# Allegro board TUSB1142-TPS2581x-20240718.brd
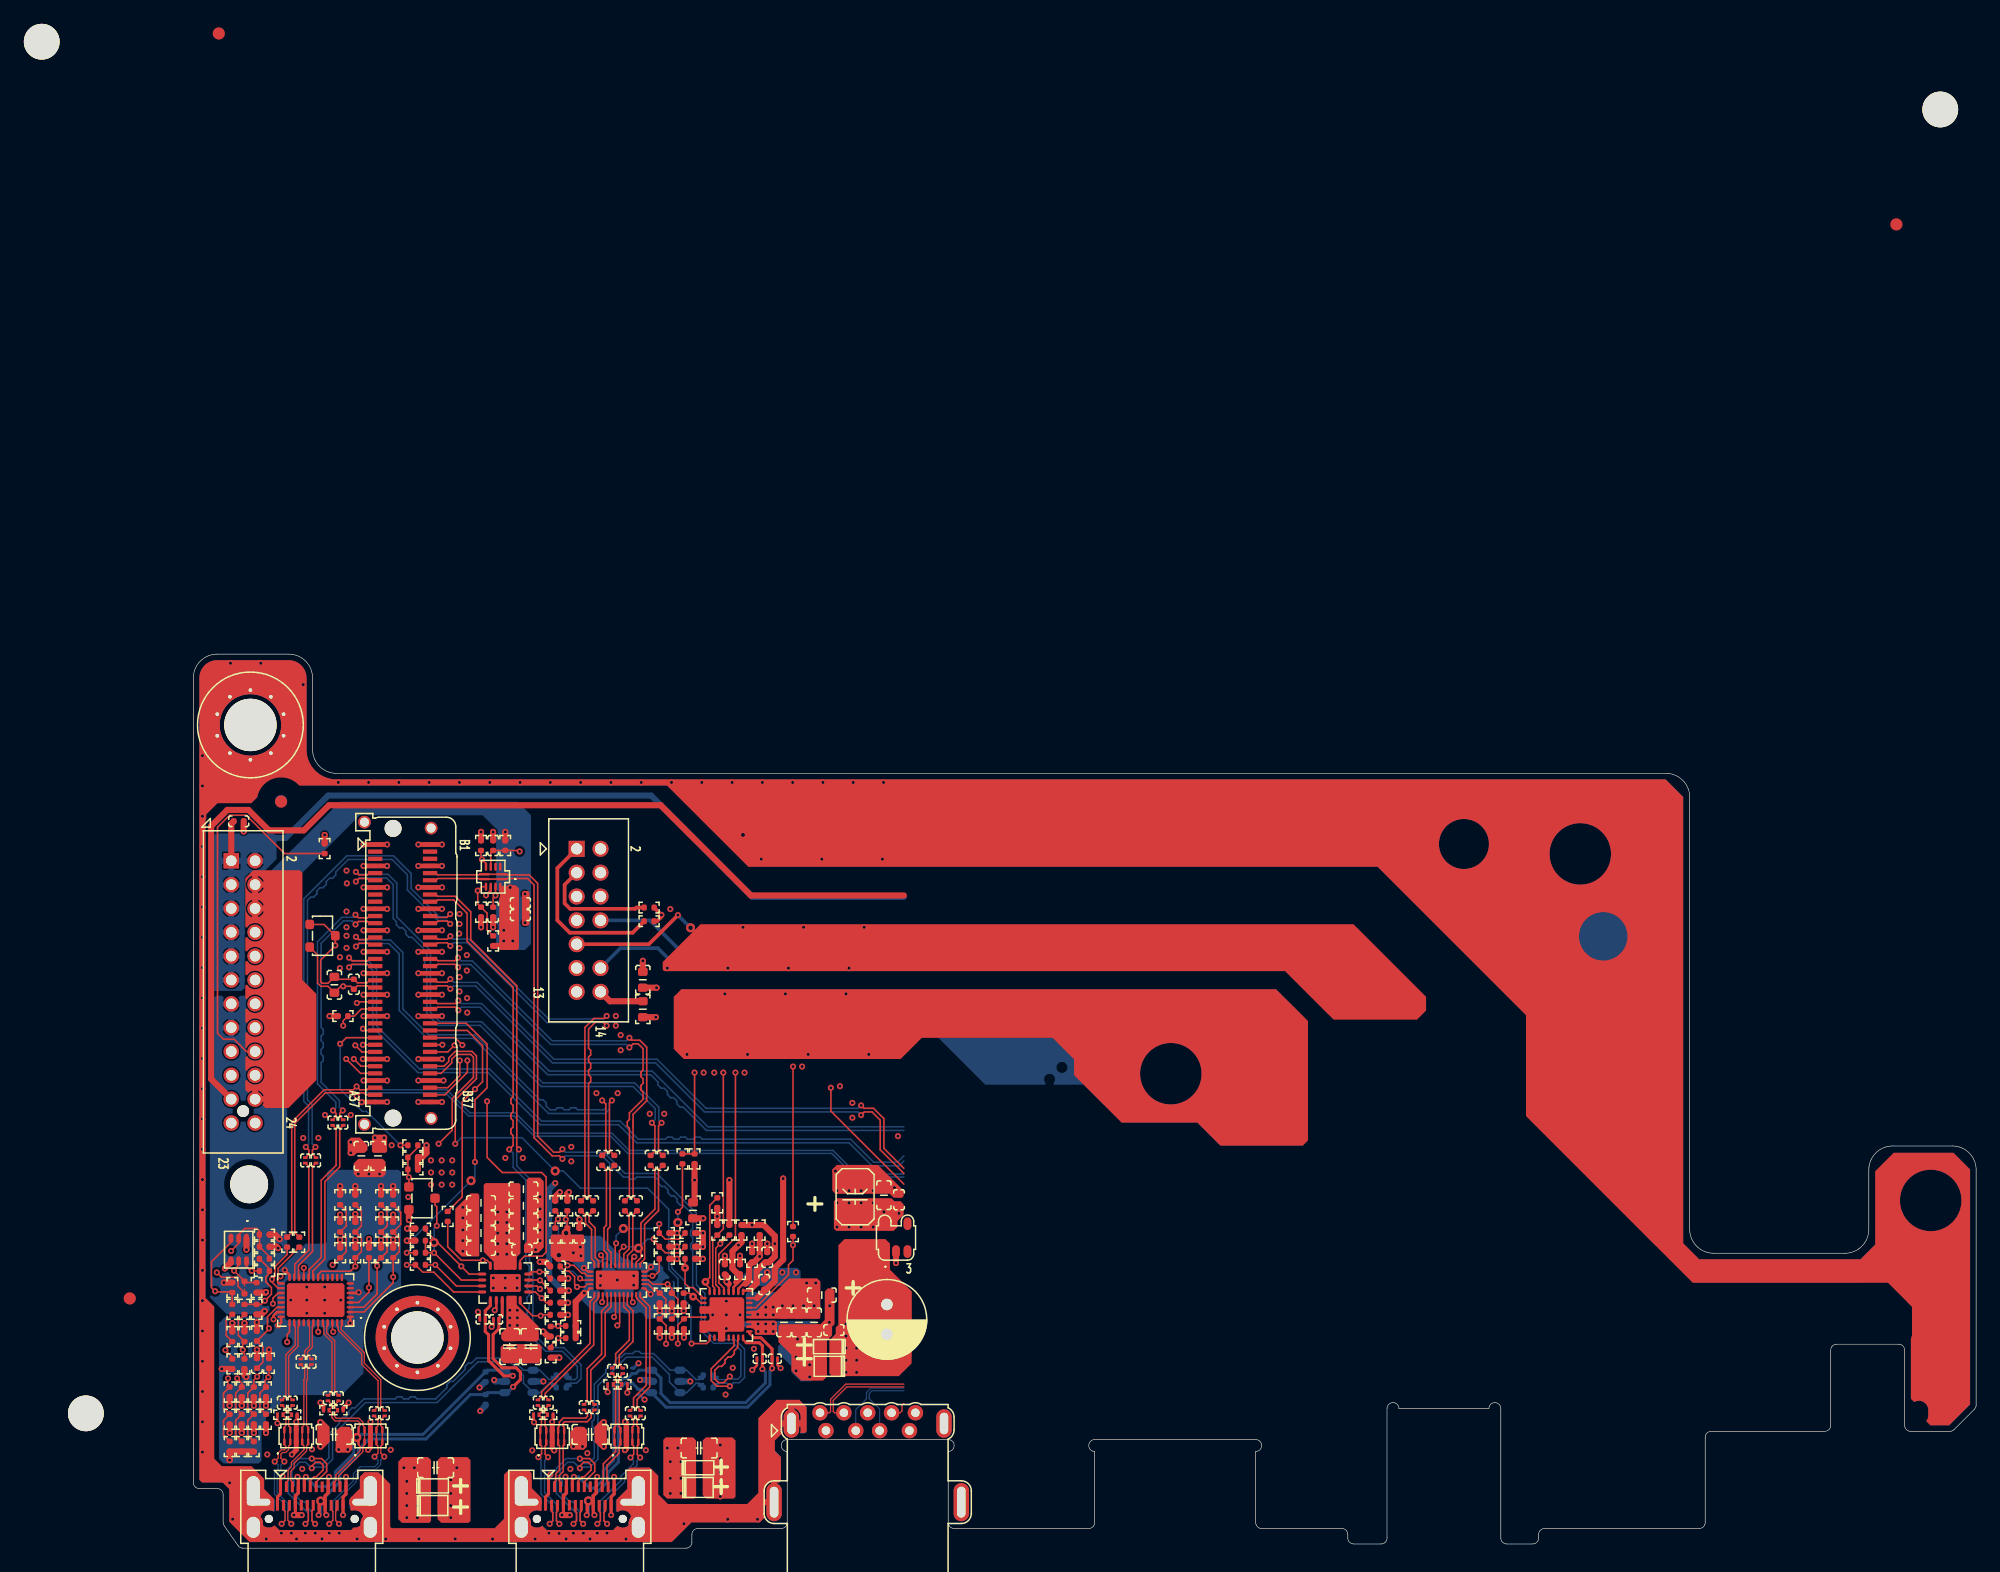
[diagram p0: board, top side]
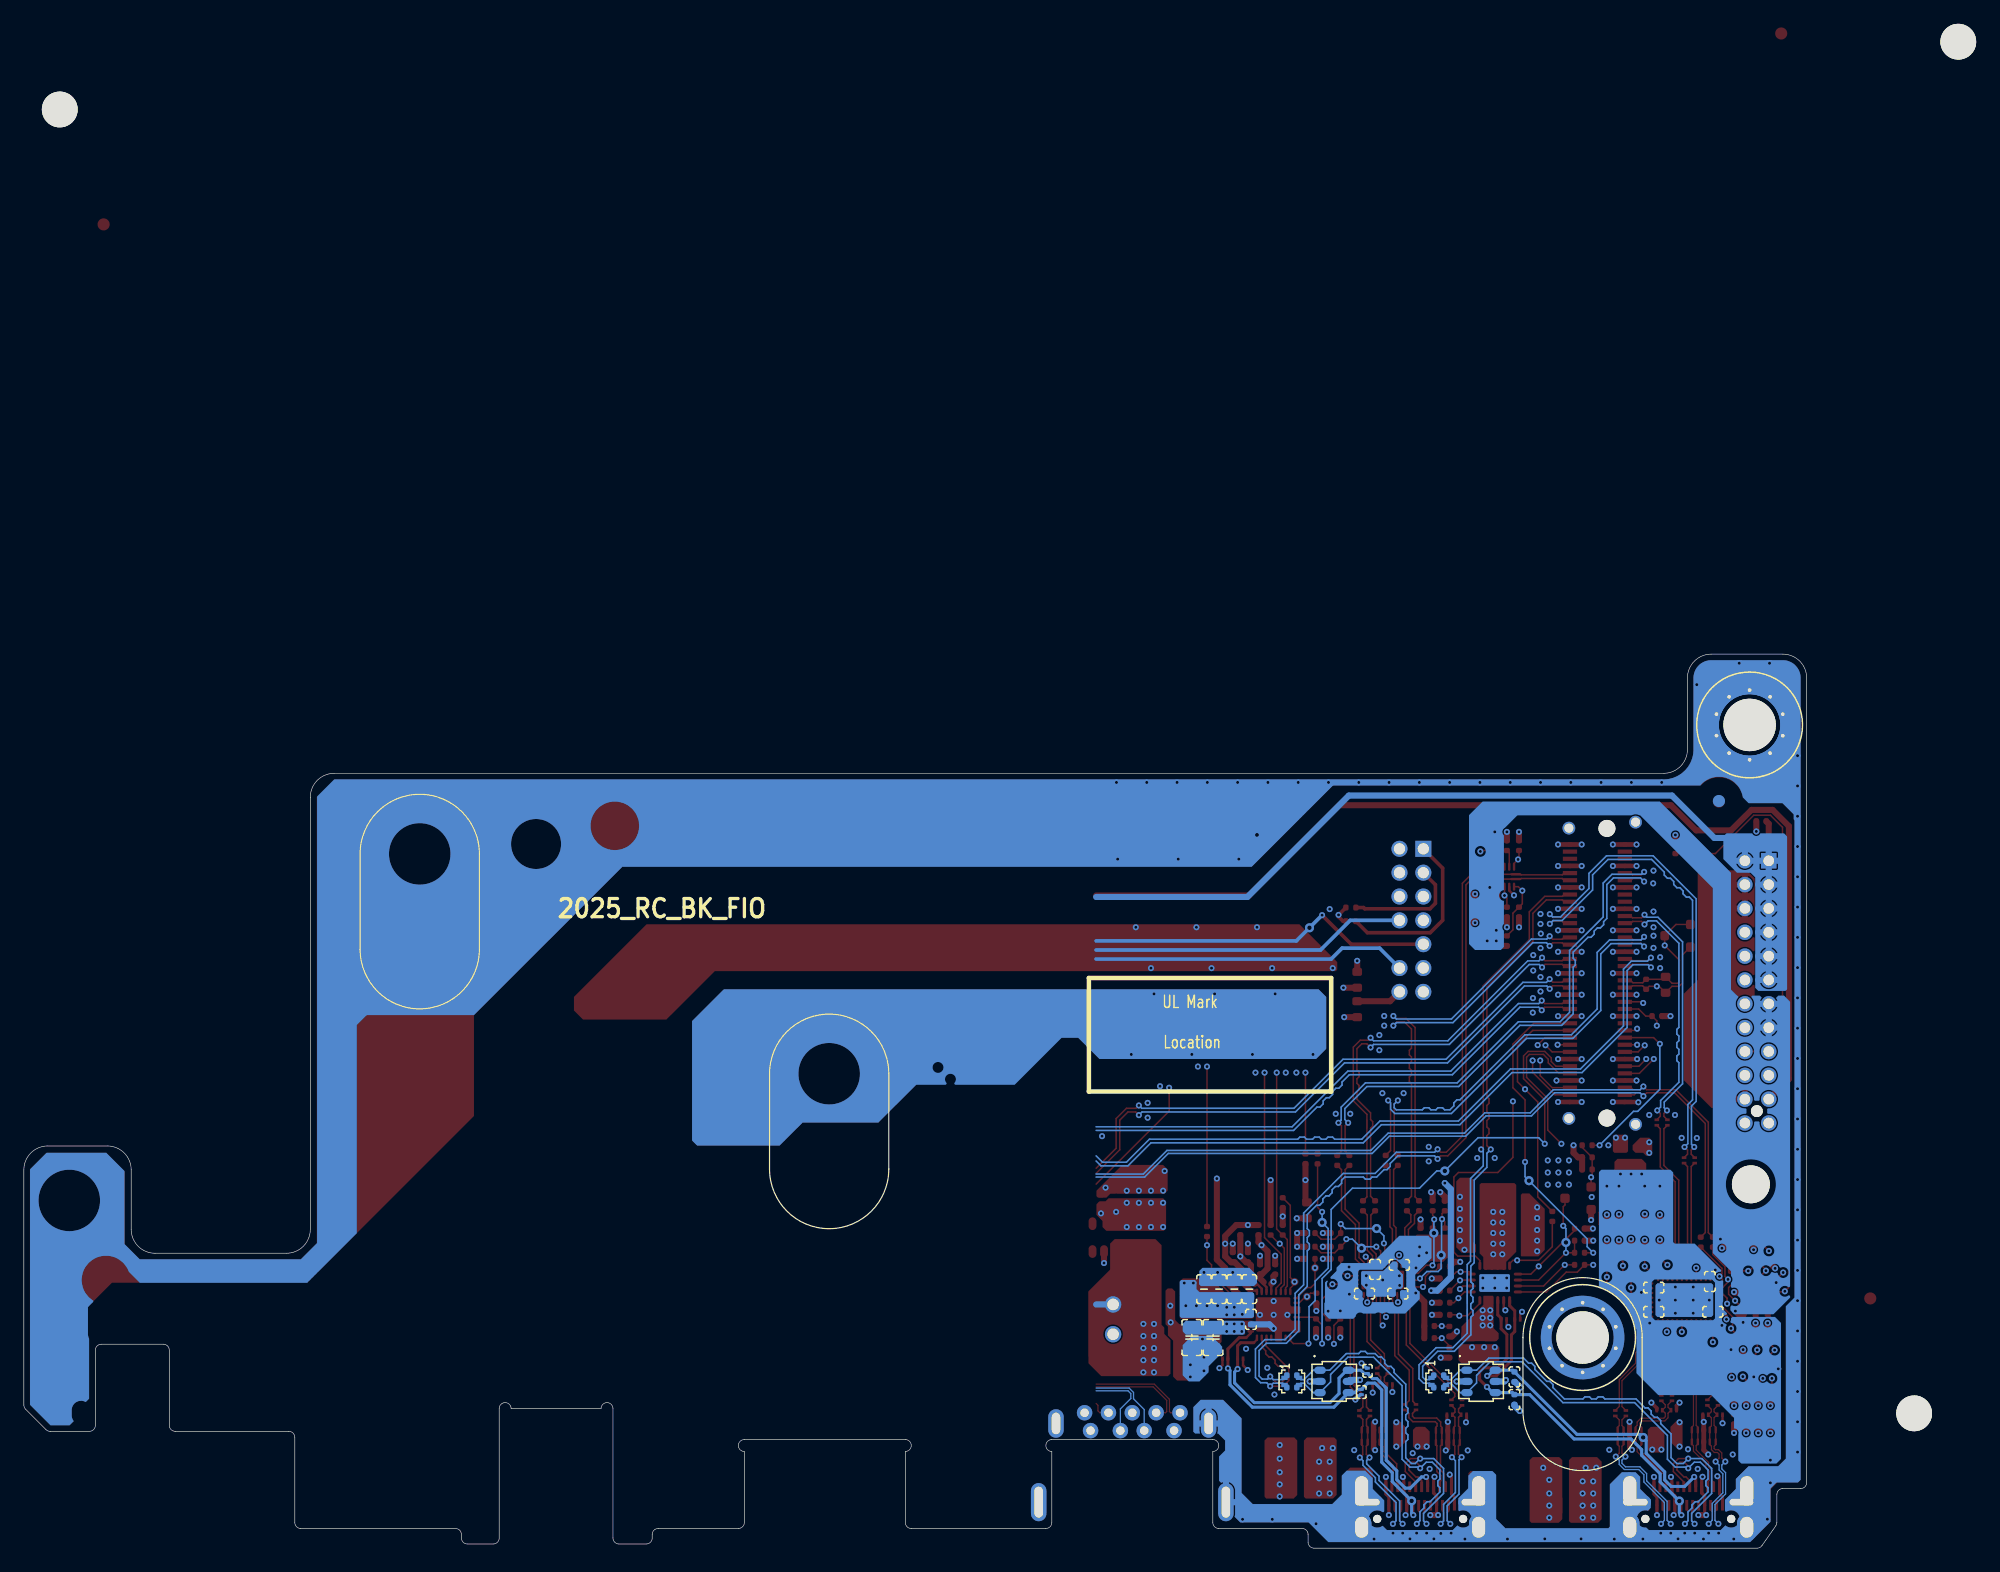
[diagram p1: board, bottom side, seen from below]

Outline 149.5 x 75 mm; copper layers: TOP, L2_GND1, L3_IN1, L4_VCC, L5_GND2, BOTTOM. Coordinates in mm from the lower left corner of the outline.
Outline path: 0,73 arc(0.59,74.41) 2,75 8,75 arc(9.41,74.41) 10,73 10,67 arc(10.59,65.59) 12,65 123.48,65 arc(124.89,64.41) 125.48,63 125.48,26.74 arc(126.07,25.33) 127.48,24.74 138.5,24.74 arc(139.91,25.33) 140.5,26.74 140.5,31.74 arc(141.09,33.15) 142.5,33.74 147.5,33.74 arc(148.91,33.15) 149.5,31.74 149.5,12.01 arc(149.46,11.82) 149.35,11.65 147.65,9.95 arc(147.48,9.84) 147.29,9.8 144,9.8 arc(143.65,9.95) 143.5,10.3 143.5,16.61 arc(143.36,16.96) 143,17.11 137.8,17.11 arc(137.45,16.96) 137.3,16.61 137.3,10.3 arc(137.16,9.95) 136.8,9.8 127.28,9.8 arc(126.93,9.65) 126.78,9.3 126.78,2.15 arc(126.63,1.8) 126.28,1.65 113.31,1.65 arc(112.96,1.5) 112.81,1.15 112.81,0.85 arc(112.66,0.5) 112.31,0.35 110.14,0.35 arc(109.79,0.5) 109.64,0.85 109.64,11.71 arc(109.14,12.21) 108.64,11.71 101.1,11.71 arc(100.6,12.21) 100.1,11.71 100.1,0.85 arc(99.95,0.5) 99.6,0.35 97.31,0.35 arc(96.96,0.5) 96.81,0.85 96.81,1.15 arc(96.66,1.5) 96.31,1.65 89.59,1.65 arc(89.23,1.8) 89.09,2.15 89.09,8.11 arc(89.59,8.61) 89.09,9.11 75.59,9.11 arc(75.08,8.61) 75.59,8.11 75.59,2.15 arc(75.44,1.8) 75.08,1.65 63.8,1.65 arc(63.45,1.8) 63.3,2.15 63.3,8.11 arc(63.8,8.61) 63.3,9.11 49.8,9.11 arc(49.3,8.61) 49.8,8.11 49.8,2.15 arc(49.65,1.8) 49.3,1.65 42.31,1.65 arc(41.96,1.5) 41.81,1.15 41.81,0.5 arc(41.66,0.15) 41.31,0 4.16,0 arc(3.93,0.06) 3.75,0.21 2.59,1.87 arc(2.52,2.01) 2.5,2.16 2.5,4.5 arc(2.35,4.85) 2,5 0.5,5 arc(0.15,5.15) 0,5.5 0,73

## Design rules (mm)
constraint set DEFAULT: min track width 0.127
net group I2C_BUS: nets I2C_FIO_RETIMER_SCL I2C_FIO_RETIMER_SDA
net group I2C_BUS_R: nets FIO_RETIMER_SCL FIO_RETIMER_SDA
net group TH_DIODE_FRONT_AN: nets TH_DIODE_FRONT_AN TH_DIODE_FRONT_CA
net group XTAL: nets HUB_XTLI HUB_XTLO
net group OTHER: nets 25814_DEBUG 25814_EC_IRQ 25814_EC_SCL 25814_EC_SDA A_SCL A_SCL_R A_SDA AMBER_PWR_LED# AN_USB2_PB_EQ AN_USB2_PB_VREG BPWR_DET BREATH_LED# CRITI_PCH_RSMRST# DG_USB2_PB_DC_BST DG_USB2_PB_RST# ECALIVE_LED_GATE F_EN_R FIO_EN_R FRONT_TYPEC_CC_RDY GPI_FRONT_CABLE1_N GPI_FRONT_CABLE2_N GPO_AMBER_R_N GPO_CHAR_CB GPO_CHAR_SMART_CDP GPO_WHITE_R_N HD_LED_PWR1 LD_DET# LOC_PWR MUX_SLP_S0_N OCP1 OCP2 PCH_PWRBTN_R_N PCH_SMB_OPTION_ALERT_N POWER_SW_IN# POWERSHARE_EN_N Q3400_6 Q6405_G Q6405_S REAR_TYPEC1_CC_RDY RREF SATA_LED_OUT SLP_S3_N SLP_S4_N SPI_HOLD SPI_MISO SPI_MOSI SPI_SCK SPI_SCS_N SPI_WP TPS25810_AUDIO TPS25810_DEBUG TPS25814_POL U1_A0 U1_A1 U1_AEQCFG U1_CEQ0 U1_CEQ1 U1_EQCFG U1_MODE U1_MUX_I2C_EN U1_PCH_EC_I2C_SCL_CYPD U1_PCH_EC_I2C_SDA_CYPD U1_TPS25810_POL U1_TPS25810_POL_R U1_TPS25810_UFP_R U1_VIO_SEL U3500_UFP_N U7401_CAP_EXT U7401_EN U7401_EQA U7401_EQB U7401_EQC U7401_EQD U7401_FGA U7401_FGB U7401_FGC U7401_FGD U9401_3_R U9401_5_R U9401_R USB_OC1_N_A USB_OC2_N_B USB_OC4_R_N USB_OC5_R_N USB_TYPEC_CHG USB_TYPEC_CHG_HI USB_TYPEC_CHG_HI_D USB_TYPEC_CHG_HI_EN USB_TYPEC_CHG_HI_EN_R USB_TYPEC_EN USB_TYPEC_REF USB_TYPEC_REF_RTN1 USBPWR_1_FIO_EN USBPWR_1_FIO_EN|_R USBPWR_2_F_EN USBPWR_2_F_EN_R
net group TYPEC_CC: nets AR_B_DFP_CC1 AR_B_DFP_CC2 U1_AR_A_DFP_CC1 U1_AR_A_DFP_CC2
net group W12_S12_AUDIO: nets AUD_FP_JACK_PIN5 AUD_FP_JACK_PLUG AUD_FP_JACK_PLUG_CONN AUD_FP_LINE2_JD AUD_FP_MIC2_JD AUD_FP_MIC_P AUD_FP_MICIN_IN_R_L AUD_FP_MICIN_IN_R_R AUD_FP_RING2 AUD_FP_RING2_C AUD_FP_RING2_CON AUD_FP_SLEEVE AUD_FP_SLEEVE_C AUD_FP_SLEEVE_CON AUD_FP_SLEEVE_GND AUD_LINE2_OUT_L_CON AUD_LINE2_OUT_L_R AUD_LINE2_OUT_R_CON AUD_LINE2_OUT_R_R MICN
net group W20_POWER: nets 25814_ADCIN1 25814_ADCIN2 +1P1V_5424 +1P5V_LDO +3P3V_DSW +3P3V_LDO +3P3V_MUX1_S5 +3P3V_U7401_S5 +3V_DVDD_C GPO_AMBER GPO_WHITE R0609_R R0610_R

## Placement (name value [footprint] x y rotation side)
C0510  10uF_X5R_6.3V  [C0603_H39]  37.69 47.68 90 top
C0604  100nF_X7R_16V  [C0402]  3.8 60.98 0 top
C0610  2.2nF_X7R_50V  [C0402]  13.46 47.3 270 top
C0611  100pF_X7R_50V  [C0603]  11.83 47.26 270 top
C0701  10uF_X5R_6.3V  [C0402_H28]  32.38 26.43 90 top
C0702  100nF_X7R_16V  [C0402]  34.16 23.77 0 bottom
C0703  100nF_X7R_16V  [C0402]  36.19 23.39 270 bottom
C0704  100nF_X7R_16V  [C0402]  34.28 21.35 0 bottom
C0705  100nF_X7R_16V  [C0402]  37.08 21.35 180 bottom
C0706  100nF_X5R_10V  [C0402]  39.36 32.53 270 top
C0707  100nF_X5R_10V  [C0402]  38.35 32.53 270 top
C0708  100nF_X5R_10V  [C0402]  37.21 28.72 270 top
C0709  100nF_X5R_10V  [C0402]  36.19 28.72 270 top
C0710  100nF_X5R_10V  [C0402]  35.3 32.53 270 top
C0711  100nF_X5R_10V  [C0402]  34.28 32.53 270 top
C0712  100nF_X5R_10V  [C0402]  33.52 28.72 270 top
C0713  100nF_X5R_10V  [C0402]  32.51 28.72 270 top
C0714  2.2uF_X5R_6.3V  [C0402]  30.35 23.64 180 top
C0801  22uF_X5R_6.3V  [C0603_H39]  52.7 21.23 0 top
C0802  22uF_X5R_6.3V  [C0603_H39]  50.54 21.73 90 bottom
C0803  22uF_X5R_6.3V  [C0603_H39]  49.52 18.94 270 top
C0804  22uF_X5R_6.3V  [C0603_H39]  46.73 21.73 90 bottom
C0805  22uF_X5R_6.3V  [C0603_H39]  49.27 21.73 90 bottom
C0806  22uF_X5R_6.3V  [C0603_H39]  48 21.73 90 bottom
C0807  10uF_X5R_6.3V  [C0603_H39]  50.79 18.94 270 top
C0808  10uF_X5R_6.3V  [C0603_H39]  52.06 18.94 270 top
C0809  100nF_X5R_25V  [C0402]  46.6 19.19 270 bottom
C0810  220pF_X7R_25V  [C0201]  48.76 15.89 0 top
C0811  220pF_X7R_25V  [C0201]  47.49 15.89 180 top
C0901  10uF_X7R_16V  [C0805_H57]  49.78 17.67 270 bottom
C0902  100nF_X7R_10V  [C0402]  25.14 58.95 90 top
C0903  10uF_X7R_16V  [C0805_H57]  51.56 17.67 270 bottom
C0904  330nF_X5R_25V  [C0201]  29.79 12.21 270 top
C0905  100nF_X7R_10V  [C0402]  25.14 53.36 270 top
C0907  220nF_X5R_10V  [C0201]  32.76 11.83 270 top
C0909  100nF_X7R_10V  [C0402]  27.43 53.1 0 top
C0910  220nF_X5R_10V  [C0201]  36.62 11.32 270 top
C0911  330nF_X5R_25V  [C0201]  35.12 14.88 270 top
C0912  330nF_X5R_25V  [C0201]  28.9 12.21 270 top
C0913  10uF_X7R_16V  [C0805_H57]  33.27 9.54 180 top
C0914  220nF_X5R_10V  [C0201]  33.65 11.83 270 top
C0916  1uF_X6S_6.3V  [C0402]  27.43 54.12 0 top
C0917  10uF_X7R_16V  [C0805_H57]  42.41 8.4 0 top
C0918  220nF_X5R_10V  [C0201]  37.51 11.32 270 top
C0919  330nF_X5R_25V  [C0201]  36.01 14.88 270 top
C1001  220nF_X5R_10V  [C0201_H13]  9.39 32.53 90 top
C1002  220nF_X5R_10V  [C0201_H13]  10.28 32.53 90 top
C1003  220nF_X5R_10V  [C0201_H13]  11.68 35.7 90 top
C1004  220nF_X5R_10V  [C0201_H13]  12.57 35.7 90 top
C1009  220nF_X7R_16V  [C0402]  5.33 15.51 270 top
C1010  10uF_X5R_6.3V  [C0603_H39]  14.09 32.91 90 top
C1011  100nF_X7R_25V  [C0402]  12.82 19.83 0 bottom
C1012  100nF_X7R_25V  [C0402]  8.12 22.37 90 bottom
C1013  100nF_X7R_25V  [C0402]  7.87 19.83 180 bottom
C1014  100nF_X7R_25V  [C0402]  12.82 21.86 0 bottom
C1105  22uF_X5R_6.3V  [C0603_H39]  24.12 25.16 180 top
C1106  22uF_X5R_6.3V  [C0603_H39]  27.68 26.18 0 top
C1107  22uF_X5R_6.3V  [C0603_H39]  24.12 28.97 180 top
C1108  22uF_X5R_6.3V  [C0603_H39]  27.68 30.12 0 top
C1109  22uF_X5R_6.3V  [C0603_H39]  24.12 27.7 180 top
C1110  22uF_X5R_6.3V  [C0603_H39]  24.12 26.43 180 top
C1111  10uF_X5R_6.3V  [C0603_H39]  27.68 27.45 0 top
C1112  10uF_X5R_6.3V  [C0603_H39]  27.68 28.72 0 top
C1113  100nF_X5R_25V  [C0402]  27.55 25.04 0 top
C1114  220pF_X7R_25V  [C0201]  25.39 19.19 180 top
C1115  220pF_X7R_25V  [C0201]  24.25 19.19 180 top
C1202  330nF_X5R_25V  [C0201]  7.44 12.21 270 top
C1203  330nF_X5R_25V  [C0201]  8.33 12.21 270 top
C1207  330nF_X5R_10V  [C0402]  24.51 14.37 270 bottom
C1208  330nF_X5R_10V  [C0402]  24.51 12.46 270 bottom
C1210  10uF_X7R_16V  [C0805_H57]  11.81 9.54 0 top
C1211  10uF_X7R_16V  [C0805_H57]  26.54 16.91 270 top
C1212  10uF_X7R_16V  [C0805_H57]  20.31 6.75 0 top
C1213  10uF_X7R_16V  [C0805_H57]  28.32 16.91 270 top
C1402  D5V0H1U2LP1610-7  [DFN_2_49_63X39_AK]  53.21 15.26 180 top
C1403  BZX584B5V6_R1_00001_5mA  [SOD_523_AK]  53.21 16.91 180 top
C1407  100nF_X7R_16V  [C0402]  59.18 29.23 90 top
C1410  220uF_CP_6.3V  [CTB_H79]  55.49 29.48 270 top
C1413  1uF_X7R_16V  [C0603_H35]  57.91 29.61 90 top
C1416  100nF_X7R_10V  [C0402]  53.72 18.31 180 top
C1505  330nF_X5R_25V  [C0201]  12.19 12.59 270 top
C1506  330nF_X5R_25V  [C0201]  11.3 12.59 270 top
C3406  220nF_X5R_10V  [C0201_H13]  16.05 11.32 270 top
C3407  220nF_X5R_10V  [C0201_H13]  15.16 11.32 270 top
C3408  220nF_X5R_10V  [C0201_H13]  9.9 15.64 270 top
C3409  220nF_X5R_10V  [C0201_H13]  9.01 15.64 270 top
C3410  220pF_X7R_25V  [C0201]  37.33 13.1 270 bottom
C3411  220pF_X7R_25V  [C0201]  36.82 14.88 90 bottom
C3414  10uF_X5R_10V  [C0402_H28]  47.87 22.12 270 top
C3417  10uF_X5R_10V  [C0402_H28]  44.57 23.39 270 top
C3418  10uF_X5R_10V  [C0402_H28]  48.13 24.4 270 top
CN1  MINI COOL EDGE_74P_30u_Black  [SAS_74__24_1016X276]  15.25 59.03 270 top
D0901  D5V0H1U2LP1610-7  [DFN_2_49_63X39_AK]  42.45 5.1 0 top
D0902  BZX584B5V6_R1_00001_5mA  [SOD_523_AK]  42.45 6.75 0 top
D1201  D5V0H1U2LP1610-7  [DFN_2_49_63X39_AK]  20.19 3.57 0 top
D1202  BZX584B5V6_R1_00001_5mA  [SOD_523_AK]  20.19 5.22 0 top
F0507  600_2A  [0603_H37]  37.69 45.21 270 top
F_TYPEC1  USBX1_Type-C_30u_Black  [USBC_24_20_406X337]  7.31 5.15 0 top
F_TYPEC2  USBX1_Type-C_30u_Black  [USBC_24_20_406X337]  29.79 5.15 0 top
FP_AUDIO  Header_2X7_K10_GF_Black  [HH_2X7_79_O10]  32.15 58.67 270 top
J1  Header_2X12_S_GF_Black  [HH_2X12_79_Z_POST1]  3.18 57.67 270 top
L0701  120_3A  [0603_H26]  41.9 28.34 270 top
L0901  CMF_90_160mA  [CK_4_49X24_V]  43.17 13.99 180 bottom
L1001  220_2.5A  [0603_H37]  15.49 32.91 270 top
L1201  CMF_90_160mA  [CK_4_49X24_V]  30.86 13.99 180 bottom
MH2  Mounting Hole  [MH_173_276_10_M2_P2]  18.79 17.67 0 top
MH6  Mounting Hole  [MH_173_276_10_M2_P2]  4.79 69.06 0 top
NOREF  V*  [unnamed]  142.81 111.05 0 top
NOREF#2  V*  [unnamed]  -5.33 20.95 0 top
NOREF#3  V*  [unnamed#2]  4.68 30.52 0 top
NOREF#4  V*  [unnamed]  2.14 127.07 0 top
NOREF#5  V*  [unnamed#2]  146.49 120.69 0 top
NOREF#6  V*  [unnamed#2]  -12.71 126.38 0 top
NOREF#7  V*  [unnamed#2]  -9.01 11.31 0 top
NOREF#8  V*  [unnamed]  7.36 62.63 0 top
NOREF#9  V*  [unnamed]  7.36 62.68 180 bottom
NOREF#10  -  [#3]  50.03 44.34 180 bottom
Q0608  MMBT3904-7-F  [SOT23_BEC_H43]  10.83 51.38 180 top
Q1001  2N7002KDWS  [SOT363V]  3.8 25.04 90 top
Q1101  L2N7002SLT1G  [SOT23_GSD_114X51]  19.17 29.35 180 top
R0502  0_5%  [R0402]  38.22 52.6 0 top
R0503  0_5%  [R0402]  38.22 53.74 0 top
R0613  200_1%  [R0402]  11.01 58.69 90 top
R0701  1K_5%  [R0402]  39.49 24.27 180 top
R0702  1K_5%  [R0402]  39.11 20.97 270 top
R0703  1K_5%  [R0402]  40.13 20.97 270 top
R0704  1K_5%  [R0402]  31.64 17.62 0 top
R0705  1K_5%  [R0402]  31.64 18.64 0 top
R0706  1K_5%  [R0402]  41.65 26.43 0 top
R0707  1K_5%  [R0402]  41.65 25.29 0 top
R0708  1K_5%  [R0402]  31.36 26.43 270 top
R0709  1K_5%  [R0402]  30.35 26.43 270 top
R0710  68K_1%  [R0402]  39.11 18.81 90 top
R0711  68K_1%  [R0402]  40.13 18.81 90 top
R0712  68K_1%  [R0402]  29.97 16.4 90 top
R0713  68K_1%  [R0402]  29.97 18.18 90 top
R0714  68K_1%  [R0402]  39.49 26.43 180 top
R0715  1K_5%  [R0402]  39.49 25.29 180 top
R0716  68K_1%  [R0402]  31.36 28.72 270 top
R0717  68K_1%  [R0402]  30.35 28.72 270 top
R0812  10K_5%  [R0402]  42.03 32.66 90 top
R0901  220K_5%  [R0201]  29.94 11.19 0 top
R0902  220K_5%  [R0201]  28.75 11.19 180 top
R0903  220K_5%  [R0201]  34.97 13.73 180 top
R0904  220K_5%  [R0201]  36.16 13.73 0 top
R0905  0_5%  [R0402]  43.17 14.5 180 bottom
R0906  0_5%  [R0402]  43.17 13.48 180 bottom
R0907  29.4K_1%  [R0402]  25.14 50.94 90 top
R0908  29.4K_1%  [R0402]  24.12 53.36 270 top
R0909  3.83K_1%  [R0402]  24.12 58.95 90 top
R0910  11K_1%  [R0402]  26.16 58.95 270 top
R1001  1K_5%  [R0402]  4.06 13.1 90 top
R1002  1K_5%  [R0402]  6.09 10.81 90 top
R1003  1K_5%  [R0402]  13.58 24.78 270 top
R1004  1K_5%  [R0402]  5.33 17.8 90 top
R1005  1K_5%  [R0402]  15.74 29.23 90 top
R1006  2.2K_5%  [R0402]  4.29 15.46 270 top
R1007  0_5%  [R0402]  8.88 25.67 270 top
R1008  2.2K_5%  [R0402]  3.27 15.46 270 top
R1009  0_5%  [R0402]  7.87 25.67 270 top
R1010  4.7K_5%  [R0402]  3.27 17.75 270 top
R1011  4.7K_5%  [R0402]  4.29 17.75 270 top
R1012  0_5%  [R0402]  3.27 20.03 270 top
R1013  0_5%  [R0402]  4.29 20.03 270 top
R1014  10K_5%  [R0402]  5.3 20.03 270 top
R1015  10K_5%  [R0402]  3.27 21.86 90 top
R1016  100K_1%  [R0402]  5.3 21.86 90 top
R1017  100K_1%  [R0402]  5.96 25.29 180 top
R1018  0_5%  [R0402]  5.96 23.26 180 top
R1019  0_5%  [R0402]  5.96 24.27 0 top
R1020  20K_5%  [R0402]  16.76 24.78 270 top
R1021  1K_5%  [R0402]  3.04 8.53 270 top
R1022  20K_5%  [R0402]  3.04 13.1 90 top
R1023  1K_5%  [R0402]  4.06 8.53 270 top
R1024  20K_5%  [R0402]  4.06 10.81 90 top
R1025  1K_5%  [R0402]  6.34 15.51 90 top
R1026  20K_5%  [R0402]  6.09 13.1 90 top
R1027  1K_5%  [R0402]  13.58 29.23 90 top
R1028  20K_5%  [R0402]  13.58 26.94 270 top
R1029  1K_5%  [R0402]  5.07 10.81 90 top
R1030  20K_5%  [R0402]  15.74 26.94 270 top
R1031  1K_5%  [R0402]  12.31 26.94 270 top
R1032  20K_5%  [R0402]  12.31 24.78 270 top
R1033  20K_5%  [R0402]  5.07 13.1 90 top
R1034  1K_5%  [R0402]  5.07 8.53 270 top
R1035  1K_5%  [R0402]  12.31 29.23 90 top
R1036  1K_5%  [R0402]  16.76 29.23 90 top
R1037  1K_5%  [R0402]  15.74 24.78 270 top
R1038  1K_5%  [R0402]  16.76 26.94 270 top
R1039  1K_5%  [R0402]  3.04 10.81 90 top
R1040  10K_5%  [R0402]  14.73 24.78 270 top
R1101  SHORT-PAD-4  [R0402_S4MIL_MVB]  4.29 21.86 90 top
R1102  0_5%  [R0402]  19.04 24.78 0 top
R1103  10K_5%  [R0402]  5.96 26.31 0 top
R1104  100K_5%  [R0402]  30.35 21.61 0 top
R1105  0_5%  [R0402]  21.33 27.83 270 top
R1106  100K_5%  [R0402]  30.35 22.62 0 top
R1107  100K_5%  [R0402]  19.04 26.81 0 top
R1108  100K_5%  [R0402]  19.04 25.8 0 top
R1109  100K_5%  [R0402]  30.35 19.58 180 top
R1110  100K_5%  [R0402]  30.35 20.59 180 top
R1111  100K_1%  [R0402]  19.04 23.77 0 top
R1112  10K_5%  [R0402]  18.41 31.77 180 top
R1201  220K_5%  [R0201]  12.34 11.57 0 top
R1202  220K_5%  [R0201]  11.14 11.57 180 top
R1203  220K_5%  [R0201]  7.28 11.19 180 top
R1204  220K_5%  [R0201]  8.48 11.19 0 top
R1205  0_5%  [R0402]  30.86 13.48 180 bottom
R1206  0_5%  [R0402]  30.86 14.5 180 bottom
R7422  200_1%  [R0402]  12.55 44.64 0 top
R7423  10K_5%  [R0402]  18.41 32.78 180 top
R7425  10K_5%  [R0402]  44.95 26.69 270 top
R7426  100K_5%  [R0402]  45.97 26.69 90 top
R7427  100K_5%  [R0402]  47.49 26.69 90 top
R7428  100K_5%  [R0402]  45.84 23.39 270 top
R7429  100K_5%  [R0402]  46.86 24.4 270 top
R7430  10K_5%  [R0402]  43.94 26.69 270 top
R7431  10K_5%  [R0402]  41.14 18.81 90 top
R7437  2.2K_5%  [R0402]  43.94 28.97 270 top
R7439  2.2K_5%  [R0402]  41.65 24.27 0 top
R7440  10K_5%  [R0402]  41.12 20.97 90 top
R74424  0_5%  [R0402]  18.41 33.8 180 top
R74425  0_5%  [R0402]  41.02 32.66 270 top
R74426  0_5%  [R0402]  50.29 26.56 270 top
TC1401  100uF_CP_16V  [CE25D63H60]  58.16 19.19 270 top
TP1  probe  [TPC26B_50]  42.95 22.34 270 top
TP2  probe  [TPC26B_50]  41.23 23.51 90 top
TP3  probe  [TPC26B_50]  41.9 21.1 270 top
U0701  PI3EQX2024ZTFEX  [UQFN_34_14_177X98_TH137X58]  35.55 22.5 180 top
U0801  TPS25814RSMR  [QFN_32_16_157_TH109_V5]  44.7 19.58 180 top
U0901  AZ1143-04F.R7G_16KV  [SLP10C_H24]  36.32 9.4 0 top
U0902  AZ1143-04F.R7G_16KV  [SLP10C_H24]  30.09 9.36 0 top
U0903  TUSB212RWBR  [X2QFN_12_16_63]  25.14 56.33 90 top
U0905  AZC199-04S.R7G_16KV  [SOT23_6]  39.62 13.99 0 bottom
U1001  TUSB1142IRNQR  [QFN_40_16_236X157_TH184X105]  10.26 20.81 90 top
U1101  TPS25810RVCR  [QFN_20_20_157X118_TH95X56]  26.16 22.24 180 top
U1201  AZ1143-04F.R7G_16KV  [SLP10C_H24]  14.85 9.42 0 top
U1202  AZ1143-04F.R7G_16KV  [SLP10C_H24]  8.63 9.42 0 top
U1203  AZC199-04S.R7G_16KV  [SOT23_6]  27.3 13.99 0 bottom
U1402  RT9742CGJ5F  [TSOT23_5_H39]  58.92 26.05 270 top
USB3_F1  USB3X1_15u_Blue  [USB3_9_516X551_1]  53.05 9.86 0 top

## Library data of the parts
C0510 C0604 C0610 C0611 C0701 C0702 C0703 C0704 C0705 C0706 C0707 C0708 C0709 C0710 C0711 C0712 C0713 C0714 C0801 C0802 C0803 C0804 C0805 C0806 C0807 C0808 C0809 C0810 C0811 C0901 C0902 C0903 C0904 C0905 C0907 C0909 C0910 C0911 C0912 C0913 C0914 C0916 C0917 C0918 C0919 C1001-C1004 C1009-C1014 C1105-C1115 C1202 C1203 C1207 C1208 C1210-C1213 C1407 C1413 C1416 C1505 C1506 C3406-C3411 C3414 C3417 C3418 = CAP_DELL
C1402 D0901 D1201 = TVS_2PIN_DELL
C1403 D0902 D1202 = ZENER_2PIN_DELL
C1410 TC1401 = ECAP_DELL
CN1 = MCIO_74pin_dell
F0507 L0701 L1001 = FB_DELL
F_TYPEC1 = USB_TYPE_C_SMD_32P_DELL
F_TYPEC2 = USB_TYPE_C_SMD_32P
FP_AUDIO = Header_2x7_K10_DELL
J1 = HEADER_2X12_POST1_DELL
L0901 L1201 = COMMON CHOKE_1_DELL
MH2 MH6 = MTG-HOLE-8_1
Q0608 = NPN_DELL
Q1001 = DUAL_MOS_N_6P_3_DELL
Q1101 = MOSFET_N_DELL
R0502 R0503 R0613 R0701 R0702 R0703 R0704 R0705 R0706 R0707 R0708 R0709 R0710 R0711 R0712 R0713 R0714 R0715 R0716 R0717 R0812 R0901 R0902 R0903 R0904 R0905 R0906 R0907 R0908 R0909 R0910 R1001-R1040 R1102-R1112 R1201-R1206 R7422 R7423 R7425-R7431 R7437 R7439 R7440 R74424-R74426 = RES_DELL
R1101 = SHORT PAD-4_DELL
TP1-TP3 = TEST_POINT_0
U0701 = PI3EQX2024ZTFEX_34PIN_DELL
U0801 = TPS25814RSMR_32P_DELL
U0901 U0902 U1201 U1202 = AZ1143-04F_10PIN_DELL
U0903 = TUSB212RWBR_0
U0905 U1203 = AZC199-04S.R7G_DELL
U1001 = TUSB1142IRNQR_40P_DELL
U1101 = TPS25810RVCR-1-GP
U1402 = RT9742CGJ5F_5PIN_DELL
USB3_F1 = USB3x1_9pin_DELL

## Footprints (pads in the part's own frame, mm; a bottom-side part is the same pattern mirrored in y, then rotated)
0603_H26
  custom 0.171x0.171 smd: 1(-0.668,0) 2(0.668,0)
0603_H37
  custom 0.171x0.171 smd: 1(-0.668,0) 2(0.668,0)
C0201
  rect 0.229x0.381 smd: 1(-0.229,0) 2(0.229,0)
C0201_H13
  rect 0.229x0.381 smd: 1(-0.229,0) 2(0.229,0)
C0402
  custom 0.114x0.114 smd: 1(-0.419,0) 2(0.419,0)
C0402_H28
  custom 0.114x0.114 smd: 1(-0.419,0) 2(0.419,0)
C0603
  custom 0.171x0.171 smd: 1(-0.668,0) 2(0.668,0)
C0603_H35
  custom 0.171x0.171 smd: 1(-0.668,0) 2(0.668,0)
C0603_H39
  custom 0.171x0.171 smd: 1(-0.668,0) 2(0.668,0)
C0805_H57
  custom 0.216x0.216 smd: 1(-0.88,0) 2(0.88,0)
CE25D63H60
  round 1.372 hole 0.965: 1(-1.25,0) 2(1.25,0)
CK_4_49X24_V
  rect 0.533x0.356 smd: 1(-0.612,0.3) 2(-0.612,-0.3) 3(0.612,-0.3) 4(0.612,0.3)
CTB_H79
  oval 1.27x2.794 smd: 1(1.524,0) 2(-1.524,0)
DFN_2_49_63X39_AK
  rect 0.66x1.295 smd: A(0.625,0) K(-0.625,0)
HH_2X7_79_O10
  rect 1.346x1.346 hole 0.94: 1(0,0)
  round 1.346 hole 0.94: 2(0,2) 3(2,0) 4(2,2) 5(4,0) 6(4,2) 7(6,0) 8(6,2) 9(8,0) 11(10,0) 12(10,2) 13(12,0) 14(12,2)
HH_2X12_79_Z_POST1
  round 0.991 hole 0.991 unplated: (21,1)
  rect 1.295x1.295 hole 0.889: 1(0,0)
  round 1.295 hole 0.889: 2(0,2) 3(2,0) 4(2,2) 5(4,0) 6(4,2) 7(6,0) 8(6,2) 9(8,0) 10(8,2) 11(10,0) 12(10,2) 13(12,0) 14(12,2) 15(14,0) 16(14,2) 17(16,0) 18(16,2) 19(18,0) 20(18,2) 21(20,0) 22(20,2) 23(22,0) 24(22,2)
MH_173_276_10_M2_P2
  round 4.394 hole 4.394 unplated: (0,0)
  round 0.508 hole 0.305: 1(0,2.921) 2(1.717,2.363) 3(2.778,0.903) 4(2.778,-0.903) 5(1.717,-2.363) 6(0,-2.921) 7(-1.717,-2.363) 8(-2.778,-0.903) 9(-2.778,0.903) 10(-1.717,2.363)
QFN_20_20_157X118_TH95X56
  oval 0.254x0.711 smd: 1(-1.25,-1.449) 2(-0.75,-1.449) 3(-0.25,-1.449) 4(0.25,-1.449) 5(0.75,-1.449) 6(1.25,-1.449) 11(1.25,1.449) 12(0.75,1.449) 13(0.25,1.449) 14(-0.25,1.449) 15(-0.75,1.449) 16(-1.25,1.449)
  oval 0.711x0.254 smd: 7(1.949,-0.75) 8(1.949,-0.25) 9(1.949,0.25) 10(1.949,0.75) 17(-1.949,0.75) 18(-1.949,0.25) 19(-1.949,-0.25) 20(-1.949,-0.75)
  rect 2.413x1.422 smd: 21(0,0)
QFN_32_16_157_TH109_V5
  oval 0.203x0.559 smd: 1(-1.4,-1.924) 2(-1,-1.924) 3(-0.6,-1.924) 4(-0.2,-1.924) 5(0.2,-1.924) 6(0.6,-1.924) 7(1,-1.924) 8(1.4,-1.924) 17(1.4,1.924) 18(1,1.924) 19(0.6,1.924) 20(0.2,1.924) 21(-0.2,1.924) 22(-0.6,1.924) 23(-1,1.924) 24(-1.4,1.924)
  oval 0.559x0.203 smd: 9(1.924,-1.4) 10(1.924,-1) 11(1.924,-0.6) 12(1.924,-0.2) 13(1.924,0.2) 14(1.924,0.6) 15(1.924,1) 16(1.924,1.4) 25(-1.924,1.4) 26(-1.924,1) 27(-1.924,0.6) 28(-1.924,0.2) 29(-1.924,-0.2) 30(-1.924,-0.6) 31(-1.924,-1) 32(-1.924,-1.4)
  rect 2.769x2.769 smd: 33(0,0)
QFN_40_16_236X157_TH184X105
  oval 0.203x0.61 smd: 1(-1.4,-2.898) 2(-1,-2.898) 3(-0.6,-2.898) 4(-0.2,-2.898) 5(0.2,-2.898) 6(0.6,-2.898) 7(1,-2.898) 8(1.4,-2.898) 21(1.4,2.898) 22(1,2.898) 23(0.6,2.898) 24(0.2,2.898) 25(-0.2,2.898) 26(-0.6,2.898) 27(-1,2.898) 28(-1.4,2.898)
  oval 0.61x0.203 smd: 9(1.898,-2.2) 10(1.898,-1.8) 11(1.898,-1.4) 12(1.898,-1) 13(1.898,-0.6) 14(1.898,-0.2) 15(1.898,0.2) 16(1.898,0.6) 17(1.898,1) 18(1.898,1.4) 19(1.898,1.8) 20(1.898,2.2) 29(-1.898,2.2) 30(-1.898,1.8) 31(-1.898,1.4) 32(-1.898,1) 33(-1.898,0.6) 34(-1.898,0.2) 35(-1.898,-0.2) 36(-1.898,-0.6) 37(-1.898,-1) 38(-1.898,-1.4) 39(-1.898,-1.8) 40(-1.898,-2.2)
  rect 2.667x4.674 smd: 41(0,0)
R0201
  rect 0.229x0.381 smd: 1(-0.229,0) 2(0.229,0)
R0402
  custom 0.114x0.114 smd: 1(-0.419,0) 2(0.419,0)
R0402_S4MIL_MVB
  custom 0.127x0.127 smd: 1(-0.419,0) 2(0.419,0)
SAS_74__24_1016X276
  round 1.422 hole 1.422 unplated: (-1.35,1.5) (22.95,1.5)
  rect 0.356x1.194 smd: A1(0,0) A2(0.6,0) A3(1.2,0) A4(1.8,0) A5(2.4,0) A6(3,0) A7(3.6,0) A8(4.2,0) A9(4.8,0) A10(5.4,0) A11(6,0) A12(6.6,0) A13(7.2,0) A14(7.8,0) A15(8.4,0) A16(9,0) A17(9.6,0) A18(10.2,0) A19(10.8,0) A20(11.4,0) A21(12,0) A22(12.6,0) A23(13.2,0) A24(13.8,0) A25(14.4,0) A26(15,0) A27(15.6,0) A28(16.2,0) A29(16.8,0) A30(17.4,0) A31(18,0) A32(18.6,0) A33(19.2,0) A34(19.8,0) A35(20.4,0) A36(21,0) A37(21.6,0) B1(0,4.6) B2(0.6,4.6) B3(1.2,4.6) B4(1.8,4.6) B5(2.4,4.6) B6(3,4.6) B7(3.6,4.6) B8(4.2,4.6) B9(4.8,4.6) B10(5.4,4.6) B11(6,4.6) B12(6.6,4.6) B13(7.2,4.6) B14(7.8,4.6) B15(8.4,4.6) B16(9,4.6) B17(9.6,4.6) B18(10.2,4.6) B19(10.8,4.6) B20(11.4,4.6) B21(12,4.6) B22(12.6,4.6) B23(13.2,4.6) B24(13.8,4.6) B25(14.4,4.6) B26(15,4.6) B27(15.6,4.6) B28(16.2,4.6) B29(16.8,4.6) B30(17.4,4.6) B31(18,4.6) B32(18.6,4.6) B33(19.2,4.6) B34(19.8,4.6) B35(20.4,4.6) B36(21,4.6) B37(21.6,4.6)
  round 1.067 hole 0.762: POST1(-1.875,-0.9) POST2(23.475,-0.9) POST3(-1.375,4.69) POST4(22.975,4.69)
SLP10C_H24
  oval 0.203x0.61 smd: 1(-1,-0.495) 2(-0.5,-0.495) 4(0.5,-0.495) 5(1.001,-0.495) 6(1.001,0.495) 7(0.5,0.495) 9(-0.5,0.495) 10(-1,0.495)
  oval 0.406x0.61 smd: 3(0,-0.495) 8(0,0.495)
SOD_523_AK
  rect 0.61x0.711 smd: A(0.7,0) K(-0.7,0)
SOT23_6
  oval 0.965x0.61 smd: 1(1.194,-0.94) 2(1.194,0) 3(1.194,0.94) 4(-1.194,0.94) 5(-1.194,0) 6(-1.194,-0.94)
SOT23_BEC_H43
  custom 0.182x0.182 smd: B(1.074,-0.946) C(-1.074,0) E(1.074,0.95)
SOT23_GSD_114X51
  custom 0.195x0.195 smd: D(-1.095,0) G(1.095,-0.946) S(1.095,0.95)
SOT363V
  oval 0.787x0.406 smd: 1(0.953,-0.65) 2(0.953,0) 3(0.953,0.65) 4(-0.953,0.65) 5(-0.953,0) 6(-0.953,-0.65)
TPC26B_50
  round 0.66 smd: 1(0,0)
TSOT23_5_H39
  oval 1.067x0.66 smd: 1(1.168,-0.94) 2(1.168,0) 3(1.168,0.965) 4(-1.168,0.965) 5(-1.168,-0.94)
unnamed
  round 1.016 smd: 1(0,0)
unnamed#2
  round 3.175 hole 3.175 unplated: (0,0)
UQFN_34_14_177X98_TH137X58
  oval 0.165x0.457 smd: 1(-1.925,-1.225) 2(-1.575,-1.225) 3(-1.225,-1.225) 4(-0.875,-1.225) 5(-0.525,-1.225) 6(-0.175,-1.225) 7(0.175,-1.225) 8(0.525,-1.225) 9(0.875,-1.225) 10(1.225,-1.225) 11(1.575,-1.225) 12(1.925,-1.225) 18(1.925,1.225) 19(1.575,1.225) 20(1.225,1.225) 21(0.875,1.225) 22(0.525,1.225) 23(0.175,1.225) 24(-0.175,1.225) 25(-0.525,1.225) 26(-0.875,1.225) 27(-1.225,1.225) 28(-1.575,1.225) 29(-1.925,1.225)
  oval 0.457x0.165 smd: 13(2.225,-0.7) 14(2.225,-0.35) 15(2.225,0) 16(2.225,0.35) 17(2.225,0.7) 30(-2.225,0.7) 31(-2.225,0.35) 32(-2.225,0) 33(-2.225,-0.35) 34(-2.225,-0.7)
  rect 3.48x1.473 smd: 35(0,0)
USB3_9_516X551_1
  round 1.295 hole 0.711: 1(0,0) 2(2.5,0) 3(4.5,0) 4(7,0) 5(7.5,1.5) 6(5.5,1.5) 7(3.5,1.5) 8(1.5,1.5) 9(-0.5,1.5)
  oval 1.295x2.388 hole 0.711x1.803: 10(-2.9,0.6) 11(9.9,0.6)
  oval 1.295x3.2 hole 0.711x2.591: 12(-4.35,-6) 13(11.35,-6)
USBC_24_20_406X337
  round 0.686 hole 0.686 unplated: (-0.975,-2.7) (6.225,-2.7)
  rect 0.254x0.889 smd: A1(0,0) A2(0.5,0) A3(1,0) A4(1.5,0) A5(2,0) A6(2.5,0) A7(3,0) A8(3.5,0) A9(4,0) A10(4.5,0) A11(5,0) A12(5.5,0) B1(5.25,-1.55) B2(4.75,-1.55) B3(4.25,-1.55) B4(3.75,-1.55) B5(3.25,-1.55) B6(2.75,-1.55) B7(2.25,-1.55) B8(1.75,-1.55) B9(1.25,-1.55) B10(0.75,-1.55) B11(0.25,-1.55) B12(-0.25,-1.55)
  oval 1.702x3.023 hole 1.092x2.464: G1(-2.28,-0.34) G2(7.53,-0.34)
  oval 1.651x2.311 hole 1.092x1.753: G3(-2.28,-3.4) G4(7.53,-3.4)
  oval 2.565x1.092 hole 1.981x0.559: G5(-1.84,-1.29)
  oval 2.642x1.092 hole 2.057x0.559: G6(7.055,-1.29)
X2QFN_12_16_63
  oval 0.203x0.889 smd: 1(-0.2,-0.737) 2(0.2,-0.737) 7(0.2,0.737) 8(-0.2,0.737)
  oval 0.686x0.203 smd: 3(0.838,-0.6) 4(0.838,-0.2) 5(0.838,0.2) 6(0.838,0.6) 9(-0.838,0.6) 10(-0.838,0.2) 11(-0.838,-0.2) 12(-0.838,-0.6)

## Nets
+3V_DVDD_C: F0507.1 FP_AUDIO.14
+5V_S5: C0604.1 C0801.1 C0802.1 C0803.1 C0804.1 C0805.1 C0806.1 C0807.1 C0808.1 C0809.1 C1105.1 C1106.1 C1107.1 C1108.1 C1109.1 C1110.1 C1111.1 C1112.1 C1113.1 C1407.1 C1410.1 C1413.1 J1.1 J1.2 J1.3 J1.5 J1.7 J1.9 J1.11 R1106.2 R1107.1 R1108.1 R1109.1 R1110.1 U0801.28 U0801.29 U1101.2 U1101.3 U1101.4 U1101.5 U1402.5
+5V_VCCPD_VBUS_F1: C1210.1 C1211.1 C1212.1 C1213.1 D1201.K(CATHODE) D1202.K(CATHODE) F_TYPEC1.A4 F_TYPEC1.A9 F_TYPEC1.B4 F_TYPEC1.B9(VBUS_4) U1101.14 U1101.15 U1203.5(VDD)
+5V_VCCPD_VBUS_F2: C0901.1 C0903.1 C0913.1 C0917.1 D0901.K(CATHODE) D0902.K(CATHODE) F_TYPEC2.A4 F_TYPEC2.A9 F_TYPEC2.B4 F_TYPEC2.B9(VBUS_4) U0801.26 U0801.27 U0905.5(VDD)
+12V_DSW: J1.4 J1.6 J1.22
GND: C0510.1 C0604.2 C0701.2 C0702.2 C0703.2 C0704.2 C0705.2 C0714.2 C0801.2 C0802.2 C0803.2 C0804.2 C0805.2 C0806.2 C0807.2 C0808.2 C0809.2 C0810.2 C0811.2 C0901.2 C0902.2 C0903.2 C0905.2 C0909.2 C0913.2 C0916.2 C0917.2 C1009.1 C1010.2 C1011.1 C1012.1 C1013.1 C1014.1 C1105.2 C1106.2 C1107.2 C1108.2 C1109.2 C1110.2 C1111.2 C1112.2 C1113.2 C1114.2 C1115.2 C1207.2 C1208.2 C1210.2 C1211.2 C1212.2 C1213.2 C1402.A C1403.A C1407.2 C1410.2 C1413.2 C1416.2 C3410.2 C3411.2 C3414.1 C3417.1 C3418.1 CN1.A1 CN1.A4 CN1.A7 CN1.A10 CN1.A13 CN1.A16 CN1.A19 CN1.A22 CN1.A25 CN1.A31 CN1.A34 CN1.A37 CN1.B1 CN1.B4 CN1.B7 CN1.B10 CN1.B13 CN1.B16 CN1.B19 CN1.B22 CN1.B25 CN1.B31 CN1.B34 CN1.B37 CN1.POST1 CN1.POST2 CN1.POST3 CN1.POST4 D0901.A D0902.A D1201.A D1202.A F_TYPEC1.A1 F_TYPEC1.A12 F_TYPEC1.B1 F_TYPEC1.B12 F_TYPEC1.G1 F_TYPEC1.G2 F_TYPEC1.G3 F_TYPEC1.G4 F_TYPEC1.G5 F_TYPEC1.G6 F_TYPEC2.A1 F_TYPEC2.A12 F_TYPEC2.B1 F_TYPEC2.B12 F_TYPEC2.G1 F_TYPEC2.G2 F_TYPEC2.G3 F_TYPEC2.G4 F_TYPEC2.G5 F_TYPEC2.G6 FP_AUDIO.4 J1.8 J1.10 J1.16 J1.17 J1.19 J1.20 J1.23 J1.24 MH2.1 MH2.2 MH2.3 MH2.4 MH2.5 MH2.6 MH2.7 MH2.8 MH2.9 MH2.10 MH6.1 MH6.2 MH6.3 MH6.4 MH6.5 MH6.6 MH6.7 MH6.8 MH6.9 MH6.10 Q1001.1 Q1001.4 Q1101.S R0613.2 R0701.1 R0710.1 R0711.1 R0712.1 R0713.1 R0714.1 R0715.1 R0716.1 R0717.1 R0901.2 R0902.2 R0903.2 R0904.2 R0908.2 R0909.2 R1001.1 R1002.1 R1003.1 R1010.1 R1011.1 R1016.1 R1017.1 R1020.1 R1022.1 R1024.1 R1026.1 R1028.1 R1029.1 R1030.1 R1031.1 R1032.1 R1033.1 R1037.1 R1038.1 R1039.1 R1201.2 R1202.2 R1203.2 R1204.2 R7422.1 R7428.1 R7429.1 TC1401.2 U0701.3 U0701.10 U0701.20 U0701.27 U0701.35 U0801.11 U0801.12 U0801.14 U0801.15 U0801.16 U0801.19 U0801.20 U0801.33 U0901.3 U0901.8 U0902.3 U0902.8 U0903.10 U0905.2 U1001.27 U1001.41 U1101.12 U1101.21 U1201.3 U1201.8 U1202.3 U1202.8 U1203.2 U1402.2 USB3_F1.4 USB3_F1.7 USB3_F1.10 USB3_F1.11 USB3_F1.12 USB3_F1.13
25814_ADCIN1: R7427.1 R7429.2 U0801.2
25814_ADCIN2: R7426.1 R7428.2 U0801.3
25814_DEBUG: R7425.2 U0801.6
25814_EC_IRQ: R7440.2 TP3.1(TP) U0801.10
25814_EC_SCL: R7439.1 TP2.1(TP) U0801.9
25814_EC_SDA: R7437.1 TP1.1(TP) U0801.8
+1P5V_LDO: C3417.2 U0801.4
+3P3V_DSW: J1.21
+3P3V_LDO: C3418.2 R7426.2 R7427.2 R7430.1 R7431.1 R7437.2 R7439.2 R7440.1 U0801.1
+3P3V_MUX1_S5: C1010.1 C1011.2 C1012.2 C1013.2 C1014.2 L1001.2(S) R1004.2 R1005.2 R1006.2 R1008.2 R1021.2 R1023.2 R1025.2 R1027.2 R1034.2 R1035.2 R1036.2 U1001.1 U1001.6 U1001.20 U1001.28
+3P3V_S0: F0507.2(S) J1.12 J1.14
+3P3V_S5: C0909.1 C0916.1 C3414.2 J1.13 J1.15 L0701.1 L1001.1 R0812.1 R0907.1 R0910.1 R1014.2 R1015.2 R1040.1 R1103.2 R1104.2 R1112.1 R7423.1 R7425.1 U0801.32(VIN_3V3) U0903.12
+3P3V_U7401_S5: C0701.1 C0702.1 C0703.1 C0704.1 C0705.1 L0701.2(S) R0702.2 R0703.2 R0704.2 R0705.2 R0706.2 R0707.2 R0708.2 R0709.2 U0701.13 U0701.17 U0701.30 U0701.34(VDD4)
A_UDN_SW: F_TYPEC2.A7 F_TYPEC2.B7 L0901.4 R0905.2 U0905.1
A_UDP_SW: F_TYPEC2.A6 F_TYPEC2.B6 L0901.3 R0906.2 U0905.3
A_URXN_SW1_R: C0904.2 F_TYPEC2.B10 R0901.1 U0902.2 U0902.9
A_URXN_SW2_R: C0911.2 F_TYPEC2.A10 R0903.1 U0901.1 U0901.10
A_URXP_SW1_R: C0912.2 F_TYPEC2.B11 R0902.1 U0902.1 U0902.10
A_URXP_SW2_R: C0919.2 F_TYPEC2.A11 R0904.1 U0901.2 U0901.9
A_UTXN_SW1_R: C0914.2 F_TYPEC2.A3 U0902.5 U0902.6(NC4)
A_UTXN_SW2_R: C0910.2 F_TYPEC2.B3 U0901.4 U0901.7
A_UTXP_SW1_R: C0907.2 F_TYPEC2.A2 U0902.4 U0902.7
A_UTXP_SW2_R: C0918.2 F_TYPEC2.B2 U0901.5 U0901.6(NC4)
AMBER_PWR_LED#: CN1.B36(TX7-)
AN_USB2_PB_EQ: R0909.1 U0903.6
AN_USB2_PB_VREG: C0905.1 U0903.11(VREG)
AR_B_DFP_CC1: C0811.1 C3411.1 F_TYPEC2.A5 U0801.24 U0905.6
AR_B_DFP_CC2: C0810.1 C3410.1 F_TYPEC2.B5 U0801.25 U0905.4
AR_U2DM_A_ESD: F_TYPEC1.A7 F_TYPEC1.B7 L1201.4 R1206.2 U1203.1
AR_U2DP_A_ESD: F_TYPEC1.A6 F_TYPEC1.B6 L1201.3 R1205.2 U1203.3
AR_U3RXN_A_ESD_1: C1203.2 F_TYPEC1.B10 R1204.1 U1202.2 U1202.9
AR_U3RXN_A_ESD_2: C1506.2 F_TYPEC1.A10 R1202.1 U1201.1 U1201.10
AR_U3RXP_A_ESD_1: C1202.2 F_TYPEC1.B11 R1203.1 U1202.1 U1202.10
AR_U3RXP_A_ESD_2: C1505.2 F_TYPEC1.A11 R1201.1 U1201.2 U1201.9
AUD_AGND: C0510.2 FP_AUDIO.2 FP_AUDIO.7 FP_AUDIO.11 FP_AUDIO.13
AUD_FP_LINE2_JD: FP_AUDIO.8
AUD_FP_MIC2_JD: FP_AUDIO.6
AUD_FP_MIC_P: R0502.2 R0503.2
AUD_FP_MICIN_IN_R_L: FP_AUDIO.1 R0502.1
AUD_FP_MICIN_IN_R_R: FP_AUDIO.3 R0503.1
AUD_FP_SLEEVE_GND: FP_AUDIO.12
AUD_LINE2_OUT_L_R: FP_AUDIO.9
AUD_LINE2_OUT_R_R: FP_AUDIO.5
BREATH_LED#: CN1.B35
CRITI_PCH_RSMRST#: CN1.A30
DG_USB2_PB_DC_BST: R0907.2 R0908.1 U0903.9
DG_USB2_PB_RST#: C0902.1 R0910.2 U0903.5
ECALIVE_LED_GATE: CN1.A33
FRONT_TYPEC_CC_RDY: CN1.B33
GPI_FRONT_CABLE1_N: J1.18 R0613.1
GPI_FRONT_CABLE2_N: CN1.A24 R7422.2
GPO_CHAR_CB: CN1.B28 R0812.2 R74425.1
GPO_CHAR_SMART_CDP: CN1.B30 R74426.1
I2C_FIO_RETIMER_SCL: CN1.A36 R1007.1
I2C_FIO_RETIMER_SDA: CN1.A35 R1009.1
LD_DET#: R1106.1 U1101.20
MUX_SLP_S0_N: R1040.2 U1001.4
POWER_SW_IN#: CN1.A23
POWERSHARE_EN_N: CN1.A29 U0801.5
Q3400_6: Q1001.6 R1018.2
REAR_TYPEC1_CC_RDY: Q1001.5 R1016.2 R1101.2
SATA_LED_OUT: CN1.B29
SLP_S3_N: CN1.B26 R1102.1
SLP_S4_N: CN1.B27 R1105.1
TC_RX1N_TYPEC_1: C1203.1 U1001.31
TC_RX1P_TYPEC_1: C1202.1 U1001.30
TC_RX2N_TYPEC_1: C1506.1 U1001.36
TC_RX2P_TYPEC_1: C1505.1 U1001.37
TC_TX1N_TYPEC_1: C3408.2 F_TYPEC1.A3 U1202.5 U1202.6(NC4)
TC_TX1P_TYPEC_1: C3409.2 F_TYPEC1.A2 U1202.4 U1202.7
TC_TX2N_TYPEC_1: C3407.2 F_TYPEC1.B3 U1201.4 U1201.7
TC_TX2P_TYPEC_1: C3406.2 F_TYPEC1.B2 U1201.5 U1201.6(NC4)
TH_DIODE_FRONT_AN: C0610.2 C0611.2 CN1.A21 Q0608.E
TH_DIODE_FRONT_CA: C0610.1 C0611.1 CN1.A20 Q0608.B Q0608.C
TPS25810_AUDIO: R1110.2 U1101.17
TPS25810_DEBUG: R1109.2 U1101.16
TPS25814_POL: CN1.B32 R7431.2 U0801.13
U1_A0: R1002.2 R1025.1 R1026.2 U1001.35
U1_A1: R1020.2 R1036.1 R1038.2 U1001.2
U1_AEQCFG: R1021.1 R1022.2 R1039.2 U1001.23
U1_AR_A_DFP_CC1: C1115.1 C1207.1 F_TYPEC1.A5 U1101.11 U1203.6
U1_AR_A_DFP_CC2: C1114.1 C1208.1 F_TYPEC1.B5 U1101.13 U1203.4
U1_CEQ0: R1029.2 R1033.2 R1034.1 U1001.38
U1_CEQ1: R1001.2 R1023.1 R1024.2 U1001.29
U1_EQCFG: R1005.1 R1030.2 R1037.2 U1001.3
U1_MODE: R1031.2 R1032.2 R1035.1 U1001.17
U1_MUX_I2C_EN: C1009.2 R1004.1 U1001.26
U1_PCH_EC_I2C_SCL_CYPD: R1006.1 R1007.2 R1011.2 R1013.2 U1001.21
U1_PCH_EC_I2C_SDA_CYPD: R1008.1 R1009.2 R1010.2 R1012.2 U1001.22
U1_TPS25810_POL: Q1001.2 R1017.2 R1019.2 R1103.1 U1101.18
U1_TPS25810_POL_R: R1013.1 R1014.1 R1018.1 R1019.1
U1_TPS25810_UFP_R: Q1001.3 R1012.1 R1015.1
U1_TX1N: C3408.1 U1001.34
U1_TX1P: C3409.1 U1001.33
U1_TX2N: C3407.1 U1001.39
U1_TX2P: C3406.1 U1001.40
U1_VIO_SEL: R1003.2 R1027.1 R1028.2 U1001.14(VIO_SEL)
U3500_UFP_N: R1101.1 R1104.1 U1101.19(UFP#)
U7401_CAP_EXT: C0714.1 U0701.16
U7401_EN: R0701.2 U0701.33
U7401_EQA: R0702.1 R0710.2 U0701.31
U7401_EQB: R0704.1 R0712.2 U0701.24
U7401_EQC: R0706.1 R0714.2 U0701.7
U7401_EQD: R0708.1 R0716.2 U0701.14
U7401_FGA: R0703.1 R0711.2 U0701.32
U7401_FGB: R0705.1 R0713.2 U0701.23
U7401_FGC: R0707.1 R0715.2 U0701.6
U7401_FGD: R0709.1 R0717.2 U0701.15
USB1_USB32_RX_C_RE_N: C1002.1 U1001.18
USB1_USB32_RX_C_RE_P: C1001.1 U1001.19
USB1_USB32_TX_C_RE_N: C1004.1 U1001.15
USB1_USB32_TX_C_RE_P: C1003.1 U1001.16
USB2_P01_ESD_DN: USB3_F1.2
USB2_P01_ESD_DP: USB3_F1.3
USB3_RX1_ESD_DN: USB3_F1.5
USB3_RX1_ESD_DP: USB3_F1.6
USB3_TX1_ESD_DN: USB3_F1.8
USB3_TX1_ESD_DP: USB3_F1.9
USB3_USB32_RX_RE_N: C0904.1 U0701.19
USB3_USB32_RX_RE_P: C0912.1 U0701.18
USB3_USB32_TX_RE_N: C0914.1 U0701.22
USB3_USB32_TX_RE_P: C0907.1 U0701.21
USB4_USB32_RX_RE_N: C0911.1 U0701.25
USB4_USB32_RX_RE_P: C0919.1 U0701.26
USB4_USB32_TX_RE_N: C0910.1 U0701.28
USB4_USB32_TX_RE_P: C0918.1 U0701.29
USB7_USB20_N: CN1.B9 L1201.1 R1206.1
USB7_USB20_P: CN1.B8 L1201.2 R1205.1
USB7_USB31_RX_N: C1002.2 CN1.B12
USB7_USB31_RX_P: C1001.2 CN1.B11
USB7_USB31_TX_N: C1004.2 CN1.A12
USB7_USB31_TX_P: C1003.2 CN1.A11
USB8_USB20_N: CN1.B6 L0901.1 R0905.1 U0801.23 U0903.1 U0903.8
USB8_USB20_P: CN1.B5 L0901.2 R0906.1 U0801.22 U0903.2 U0903.7
USB8_USB31_RX_N: C0712.1 CN1.B15
USB8_USB31_RX_N_C: C0712.2 U0701.11
USB8_USB31_RX_P: C0713.1 CN1.B14
USB8_USB31_RX_P_C: C0713.2 U0701.12
USB8_USB31_TX_N: C0710.1 CN1.A15
USB8_USB31_TX_N_C: C0710.2 U0701.8
USB8_USB31_TX_P: C0711.1 CN1.A14
USB8_USB31_TX_P_C: C0711.2 U0701.9
USB9_USB31_RX_N: C0709.1 CN1.B18
USB9_USB31_RX_N_C: C0709.2 U0701.5
USB9_USB31_RX_P: C0708.1 CN1.B17
USB9_USB31_RX_P_C: C0708.2 U0701.4
USB9_USB31_TX_N: C0707.1 CN1.A6
USB9_USB31_TX_N_C: C0707.2 U0701.2
USB9_USB31_TX_P: C0706.1 CN1.A5
USB9_USB31_TX_P_C: C0706.2 U0701.1
USB10_USB20_N: CN1.B24
USB10_USB20_P: CN1.B23
USB10_USB31_RX_N: CN1.B21
USB10_USB31_RX_P: CN1.B20
USB10_USB31_TX_N: CN1.A18
USB10_USB31_TX_P: CN1.A17
USB_OC1_N_A: U1402.3
USB_OC4_R_N: CN1.A27 R7430.2 U0801.7
USB_OC5_R_N: CN1.A32 U1101.1
USB_TYPEC_CHG: R1107.2 U1101.7
USB_TYPEC_CHG_HI: Q1101.D R1102.2 R1108.2 U1101.8
USB_TYPEC_CHG_HI_D: R74425.2 U0801.17
USB_TYPEC_CHG_HI_EN: Q1101.G R1112.2 R7423.2 R74424.1
USB_TYPEC_CHG_HI_EN_R: CN1.A28 R74424.2
USB_TYPEC_EN: R1105.2 U1101.6
USB_TYPEC_REF: R1111.1 U1101.10
USB_TYPEC_REF_RTN1: R1111.2 U1101.9
USBPWR_1_F: C1402.K(CATHODE) C1403.K(CATHODE) C1416.1 TC1401.1 U1402.1(VOUT) USB3_F1.1(VBUS)
USBPWR_1_FIO_EN|_R: U1402.4
N24251455: R74426.2 U0801.30

Pads without a net: CN1 A2 A3 A8 A9 A26 B2 B3; F_TYPEC1 A8 B8; F_TYPEC2 A8 B8; NOREF 1; NOREF#2 1; NOREF#4 1; NOREF#8 1; NOREF#9 1; U0801 18 21 31; U0903 3 4; U1001 5 7 8 9 10 11 12 13 24 25 32

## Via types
v1: diameter 0.508, hole 0.254, TOP to BOTTOM, 676 vias
v2: diameter 0.762, hole 0.381, TOP to BOTTOM, 12 vias
v3: diameter 0.66, hole 0.33, TOP to BOTTOM, 1 via

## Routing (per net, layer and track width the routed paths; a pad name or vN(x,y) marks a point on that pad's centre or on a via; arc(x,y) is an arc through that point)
+3V_DVDD_C: length 3.9
  TOP w0.508: FP_AUDIO.14 34.93,45.88 F0507.1
+5V_S5: length 128.7
  TOP w0.508: C0604.1 3.18,60.77 J1.1 ; R1106.2 v1(31.44,22.62) ; R1110.1 v1(31.43,20.59) ; R1107.1 v1(17.93,26.81) ; R1109.1 v1(31.43,19.58) ; R1108.1 v1(17.9,25.8)
  L3_IN1 w0.508: 2.28,47.67 J1.11 ; J1.11 4.08,47.67 ; J1.11 3.18,48.57 ; J1.11 3.18,46.76 ; J1.3 3.18,56.57 ; J1.3 4.08,55.67 ; J1.3 3.18,54.76 ; J1.3 2.28,55.67 ; 2.28,57.67 J1.1 ; J1.1 3.18,56.76 ; J1.1 3.18,58.57 ; J1.1 4.08,57.67 ; J1.5 3.18,54.57 ; J1.5 4.08,53.67 ; J1.5 2.28,53.67 ; J1.5 3.18,52.76 ; J1.9 4.08,49.67 ; J1.9 3.18,48.76 ; J1.9 3.18,50.57 ; J1.9 2.28,49.67 ; 5.18,56.76 J1.2 ; J1.2 4.28,57.67 ; J1.2 6.08,57.67 ; J1.2 5.18,58.57 ; J1.7 4.08,51.67 ; J1.7 3.18,50.76 ; J1.7 2.28,51.67 ; J1.7 3.18,52.57
  L4_VCC w0.508: 2.55,55.03 J1.3 2.55,56.3 ; 5.82,58.3 J1.2 4.55,58.3 ; 2.55,51.03 J1.7 2.55,52.3 ; 2.55,54.3 J1.5 2.55,53.03 ; 2.55,58.3 J1.1 ; J1.1 2.55,57.03 ; J1.1 3.82,57.03 ; J1.1 3.82,58.3 ; 2.55,47.03 J1.11 2.55,48.3 ; 2.55,49.03 J1.9 2.55,50.3
  BOTTOM w0.508: 3.18,56.76 J1.1 ; J1.1 3.18,58.57 ; J1.1 2.28,57.67 ; J1.1 4.08,57.67 ; 2.28,49.67 J1.9 ; J1.9 4.08,49.67 ; J1.9 3.18,50.57 ; J1.9 3.18,48.76 ; J1.11 3.18,48.57 ; J1.11 4.08,47.67 ; J1.11 2.28,47.67 ; J1.2 5.18,58.57 ; J1.2 6.08,57.67 ; J1.2 4.28,57.67 ; J1.3 3.18,56.57 ; J1.3 4.08,55.67 ; J1.3 3.18,54.76 ; J1.3 2.28,55.67 ; 2.28,51.67 J1.7 ; J1.7 4.08,51.67 ; J1.7 3.18,50.76 ; J1.7 3.18,52.57 ; J1.5 4.08,53.67 ; J1.5 3.18,54.57 ; J1.5 2.28,53.67 ; J1.5 3.18,52.76 ; 59.58,54.63 46.9,54.63 38.39,63.14 11.3,63.14 7.74,59.58 6.47,59.58 ; C0809.1 v1(47.33,19.61)
  vias: v1(18.03,29.46) v1(19.93,32.53) v1(19.93,31.51) v1(19.93,30.5) v1(20.82,32.53) v1(20.82,31.51) v1(20.82,30.5) v1(21.71,32.53) v1(21.71,31.51) v1(21.71,30.5) v1(25.52,28.21) v1(25.52,27.32) v1(25.52,26.43) v1(25.52,25.54) v1(25.52,24.66) v1(26.28,28.21) v1(26.28,27.32) v1(26.28,26.43) v1(26.28,25.54) v1(26.28,24.66) v1(48,20.21) v1(48,19.58) v1(48.64,20.21) v1(48.64,19.58) v1(49.4,20.34) v1(50.29,20.34) v1(51.18,20.34) v1(51.43,22.24) v1(52.06,20.34) v1(52.19,22.24) v1(53.97,28.97) v1(53.97,26.94) v1(54.99,28.97) v1(54.99,26.94) v1(56,28.97) v1(56,26.94) v1(57.02,28.97) v1(57.02,26.94) v1(57.91,28.21) v1(59.18,28.08)
+5V_VCCPD_VBUS_F1: length 8.4
  TOP w0.254: v1(8.73,5.99) 8.81,5.91 F_TYPEC1.A4 ; F_TYPEC1.B4 11.06,2.88 v1(11.16,2.77) ; F_TYPEC1.A9 11.31,5.9 v1(11.38,5.98) ; v1(8.43,2.77) 8.56,2.9 F_TYPEC1.B9
  TOP w0.279: F_TYPEC1.A9 11.31,4.63 11.06,4.38 F_TYPEC1.B4 ; F_TYPEC1.B9 8.56,4.38 8.81,4.63 F_TYPEC1.A4
  TOP w0.508: v1(9.08,2.77) v1(8.43,2.77)
  BOTTOM w0.508: U1203.5 25.34,13.99 v1(25.23,14.1)
  vias: v1(10.66,10.56) v1(10.66,8.53) v1(17.65,6.75) v1(17.9,5.61) v1(17.9,4.59) v1(17.9,3.57) v1(17.9,2.56) v1(18.54,6.75) v1(18.79,5.61) v1(18.79,4.59) v1(18.79,3.57) v1(18.79,2.56) v1(26.54,19.96) v1(26.54,19.32) v1(26.54,18.69) v1(27.17,19.96) v1(27.17,19.32) v1(27.17,18.69)
+5V_VCCPD_VBUS_F2: length 8.4
  TOP w0.254: v1(31.21,5.99) 31.29,5.91 F_TYPEC2.A4 ; F_TYPEC2.B4 33.54,2.88 v1(33.64,2.77) ; v1(33.86,5.98) 33.79,5.9 F_TYPEC2.A9 ; v1(30.91,2.77) 31.04,2.9 F_TYPEC2.B9
  TOP w0.279: F_TYPEC2.B4 33.54,4.38 33.79,4.63 F_TYPEC2.A9 ; F_TYPEC2.A4 31.29,4.63 31.04,4.38 F_TYPEC2.B9
  TOP w0.508: v1(31.56,2.77) v1(30.91,2.77)
  BOTTOM w0.508: v1(37.46,14.11) 38.3,14.11 U0905.5
  vias: v1(34.41,10.56) v1(34.41,8.53) v1(39.75,8.4) v1(40,7.26) v1(40,5.86) v1(40,4.59) v1(40.63,8.4) v1(40.89,7.26) v1(40.89,5.86) v1(40.89,4.59) v1(47.37,18.81) v1(47.37,18.18) v1(48,18.81) v1(48,18.18) v1(48.64,18.81) v1(48.64,18.18)
+12V_DSW: length 7.2
  TOP w0.508: 5.18,52.76 J1.6 ; J1.6 6.08,53.67 ; J1.6 5.18,54.57 ; 6.08,37.67 J1.22 5.18,38.57 ; J1.4 5.18,56.57 ; J1.4 5.18,54.76 ; J1.4 6.08,55.67
GND: length 209.7
  TOP w0.152: U0701.27 36.78,20.7 v1(36.85,20.63) ; v1(36.98,24.45) 36.78,24.25 U0701.3 ; v1(34.28,20.64) 34.33,20.69 U0701.20 ; U0701.10 34.33,24.43 v1(34.18,24.58)
  TOP w0.203: v1(46.87,14.95) 47.26,15.34 C0811.2 ; v1(49.24,15.1) 48.99,15.36 C0810.2 ; R0904.2 v1(36.39,13.05) ; v1(6.73,19.19) 6.73,19.5 7.03,19.81 U1001.27 ; C1115.2 24.02,19.68 v1(23.87,19.83) ; v1(25.27,19.96) 25.41,20.09 U1101.12 ; R1203.2 v1(7.06,10.48) ; v1(34.74,13.1) R0903.2 ; C1114.2 25.17,18.71 v1(25.01,18.56) ; U0903.10 24.94,55.16 v1(24.54,54.77)
  TOP w0.254: F_TYPEC1.B12 7.06,4.29 7.31,4.54 F_TYPEC1.A1 7.31,5.86 v1(7.49,6.04) ; v1(35.04,2.77) F_TYPEC2.B1 35.04,4.29 35.29,4.54 F_TYPEC2.A12 v1(35.29,5.98) ; R0901.2 30.17,10.67 v1(30.09,10.6) ; v1(12.81,5.98) F_TYPEC1.A12 12.81,4.54 12.56,4.29 F_TYPEC1.B1 v1(12.56,2.77) ; F_TYPEC2.B12 29.54,4.29 29.79,4.54 F_TYPEC2.A1 29.79,6.02 v1(29.93,6.17) ; R0902.2 28.52,10.61 v1(28.57,10.56)
  TOP w0.305: v1(10.66,12.21) 10.92,11.96 R1202.2 ; R1204.2 8.71,10.67 v1(8.63,10.6) ; R1201.2 12.57,11.75 v1(13.02,12.21)
  TOP w0.381: v1(18.87,39.23) CN1.B34 v1(20.98,39.23) ; v1(18.87,37.43) CN1.B37 v1(20.85,37.43) ; v1(20.85,53.63) CN1.B10 v1(18.87,53.63) ; v1(16.25,50.03) CN1.A16 v1(14.27,50.03) ; v1(18.87,50.03) CN1.B16 v1(20.85,50.03) ; v1(14.27,46.43) CN1.A22 v1(16.25,46.43) ; v1(18.87,59.03) CN1.B1 v1(20.85,59.03) ; v1(16.25,41.03) CN1.A31 v1(14.22,41.03) ; v1(20.85,51.83) CN1.B13 v1(18.87,51.83) ; v1(14.27,59.03) CN1.A1 v1(16.25,59.03) ; v1(16.25,51.83) CN1.A13 v1(14.27,51.83) ; v1(16.25,53.63) CN1.A10 v1(14.27,53.63) ; v1(14.12,37.41) 14.14,37.43 CN1.A37 v1(16.25,37.43) ; v1(18.87,57.23) CN1.B4 v1(20.85,57.23) ; v1(20.85,44.63) CN1.B25 v1(18.87,44.63) ; v1(14.27,57.23) CN1.A4 v1(16.25,57.23) ; v1(16.25,55.43) CN1.A7 v1(14.27,55.43) ; v1(20.85,41.03) CN1.B31 v1(18.87,41.03) ; v1(16.25,48.23) CN1.A19 v1(14.27,48.23) ; v1(20.85,55.43) CN1.B7 v1(18.87,55.43) ; v1(20.85,46.43) CN1.B22 v1(18.87,46.43) ; v1(18.87,48.23) CN1.B19 v1(20.85,48.23) ; v1(14.27,39.23) CN1.A34 v1(16.25,39.23) ; v1(16.25,44.63) CN1.A25 v1(14.27,44.63)
  TOP w0.406: v1(30.09,10.6) U0902.8 U0902.3 30.09,8.37 v1(30.26,8.2) ; v1(8.26,7.86) 8.63,8.23 U1202.3 U1202.8 v1(8.63,10.6) ; v1(14.85,10.6) U1201.8 U1201.3 14.85,8.45 v1(14.66,8.25)
  TOP w0.457: v1(36.19,8.22) 36.32,8.35 U0901.3 U0901.8 36.32,10.48 v1(36.19,10.61)
  TOP w0.508: C0902.2 v1(25.14,60.09) ; R1037.1 v1(15.74,25.85) ; USB3_F1.10 51.05,10.46 ; USB3_F1.10 49.25,10.46 ; USB3_F1.10 50.15,11.91 ; C0714.2 29.55,24.02 v1(29.05,24.02) ; R0712.1 v1(30.69,15.98) ; R1038.1 v1(16.76,27.98) ; R1001.1 v1(4.06,11.96) ; R1028.1 v1(13.58,28.03) ; C3414.1 48.13,22.79 v1(48.13,23.13) ; R1033.1 v1(5.07,11.96) ; Q1001.4 3.15,23.98 v1(2.65,23.47) ; R0715.1 v1(40.57,25.29) ; Q1001.1 v1(4.45,25.04) ; R0713.1 29.75,17.76 v1(29.33,18.18) ; R0909.2 v1(24.12,60.09) ; R1010.1 v1(3.27,18.89) ; R0613.2 v1(11.01,59.83) ; C0701.2 v1(32.38,27.58) ; R1039.1 v1(3.04,9.67) ; v1(6.09,11.96) R1026.1 ; R7429.1 v1(46.86,25.54) ; R1003.1 v1(13.58,25.85) ; R7422.1 v1(11.42,44.64) ; v1(31.49,29.86) 31.36,29.74 R0716.1 ; Q1101.S v1(18.08,27.53) ; 47.8,3.86 USB3_F1.12 48.7,5.71 ; R1024.1 v1(4.06,9.67) ; R1016.1 6.05,21.44 v1(6.09,21.48) ; R0711.1 v1(40.13,17.67) ; C3418.1 v1(48.13,25.54) ; v1(7.11,25.16) 6.98,25.29 R1017.1 ; R0908.2 v1(24.12,52.09) ; R1029.1 v1(5.07,9.67) ; R0710.1 v1(39.11,17.67) ; C0604.2 v1(4.22,60.13) ; U1402.2 v1(58.92,23.92) ; R1022.1 v1(3.04,11.96) ; C0510.1 v1(38.85,47.02) ; R0717.1 30.35,29.48 v1(30.73,29.86) ; R7428.1 v1(45.84,24.53) ; R1020.1 v1(16.76,25.87) ; C0905.2 v1(25.14,52.09) ; v1(6.09,9.67) R1002.1 ; R0701.1 v1(40.57,24.27) ; R1032.1 v1(12.31,25.87) ; C3417.1 v1(44.57,24.53) ; R0714.1 v1(40.57,26.43) ; C1009.1 v1(5.33,16.65) ; R1030.1 v1(15.74,28.01) ; R1011.1 v1(4.29,18.89) ; R1031.1 v1(12.31,27.98)
  L3_IN1 w0.508: 48.7,5.71 USB3_F1.12 47.8,3.86 ; 13.73,4.81 F_TYPEC1.G2 ; F_TYPEC1.G2 14.84,6.59 ; F_TYPEC1.G2 15.94,4.81 ; 6.99,3.85 F_TYPEC1.G5 3.91,3.85 ; F_TYPEC1.G1 6.13,4.81 ; F_TYPEC1.G1 3.92,4.81 ; F_TYPEC1.G1 5.03,6.59 ; USB3_F1.10 51.05,10.46 ; USB3_F1.10 49.25,10.46 ; USB3_F1.10 50.15,11.91 ; 12.8,3.88 F_TYPEC1.G6 15.95,3.88 ; 15.94,3.16 F_TYPEC1.G4 15.94,1.75 ; F_TYPEC2.G2 38.42,4.81 ; F_TYPEC2.G2 36.21,4.81 ; F_TYPEC2.G2 37.32,6.59 ; TC1401.2 59.1,17.94 ; TC1401.2 58.16,17 ; TC1401.2 58.16,18.88 ; TC1401.2 57.22,17.94 ; 55.65,11.36 USB3_F1.7 ; USB3_F1.7 57.45,11.36 ; USB3_F1.7 56.55,12.26 ; 26.4,4.81 F_TYPEC2.G1 ; F_TYPEC2.G1 28.61,4.81 ; F_TYPEC2.G1 27.51,6.59 ; 29.47,3.85 F_TYPEC2.G5 26.39,3.85 ; 38.42,3.16 F_TYPEC2.G4 38.42,1.75 ; 35.28,3.88 F_TYPEC2.G6 38.43,3.88 ; 26.41,1.75 F_TYPEC2.G3 ; 3.93,1.75 F_TYPEC1.G3
  L4_VCC w0.508: 4,6.51 F_TYPEC1.G1 4,3.14 ; 15.88,4.58 F_TYPEC1.G6 15.88,3.14 ; 3.99,3.14 F_TYPEC1.G5 3.99,4.58 ; 63.78,11.83 USB3_F1.11 62.12,11.83 ; 38.36,3.14 F_TYPEC2.G6 38.36,4.58 ; 26.47,3.14 F_TYPEC2.G5 26.47,4.58
  BOTTOM w0.254: v1(37.84,12.46) 37.43,12.87 C3410.2 ; v1(37.33,15.51) 36.93,15.1 C3411.2
  BOTTOM w0.508: v1(44.7,18.42) 45.05,18.77 C0809.2 ; C1207.2 24.47,13.95 v1(24,13.48) ; USB3_F1.10 51.05,10.46 ; USB3_F1.10 49.25,10.46 ; USB3_F1.10 50.15,11.91 ; 47.8,3.86 USB3_F1.12 48.7,5.71 ; v1(41.68,13.99) U0905.2 ; v1(29.36,13.99) U1203.2 ; v1(24.06,11.51) 24.51,11.96 C1208.2
  vias: v1(0.77,66.48) v1(0.77,63.94) v1(0.77,61.4) v1(0.77,58.86) v1(0.77,56.32) v1(0.77,53.78) v1(0.77,51.24) v1(0.77,48.7) v1(0.77,46.16) v1(0.77,43.62) v1(0.77,41.08) v1(0.77,38.54) v1(0.77,36) v1(0.77,33.46) v1(0.77,30.92) v1(0.77,28.38) v1(0.77,25.84) v1(0.77,23.3) v1(0.77,20.76) v1(0.77,18.22) v1(0.77,15.68) v1(0.77,13.14) v1(0.77,10.6) v1(0.77,8.06) v1(3.12,74.24) v1(3.04,5.48) v1(3.3,2.43) v1(5.66,74.24) v1(6.12,0.77) v1(6.2,7.86) v1(7.39,1.26) v1(8.16,20.81) v1(8.22,1.26) v1(8.66,0.77) v1(9.14,6.65) v1(9.22,72.44) v1(9.21,34.41) v1(9.39,1.26) v1(9.51,21.91) v1(9.51,20.81) v1(9.51,19.71) v1(9.95,8.3) v1(10.23,1.26) v1(10.48,34.42) v1(10.79,0.78) v1(11.01,21.91) v1(11.01,20.81) v1(11.01,19.71) v1(11.04,36.34) v1(11.4,1.26) v1(12.16,64.24) v1(12.19,8.27) v1(12.24,1.26) v1(12.29,49.57) v1(12.29,48.66) v1(12.36,20.81) v1(12.85,56.84) v1(12.87,55.77) v1(12.85,53.41) v1(12.85,52.09) v1(12.85,51.38) v1(12.85,50.36) v1(12.95,8.27) v1(13.2,36.34) v1(13.2,34.05) v1(13.2,33.16) v1(13.74,0.77) v1(14.7,64.24) v1(16.13,0.76) v1(16.63,33.8) v1(16.55,8.25) v1(17.24,64.24) v1(18.92,0.78) v1(19.78,64.24) v1(21.58,5.73) v1(21.58,4.59) v1(21.58,3.57) v1(21.58,2.56) v1(21.97,0.78) v1(22.09,6.75) v1(22.32,64.24) v1(22.32,53.2) v1(22.32,52.37) v1(22.3,51.55) v1(22.32,50.34) v1(22.32,47.91) v1(22.32,46.7) v1(22.6,28.59) v1(22.6,27.7) v1(22.6,26.69) v1(22.6,25.8) v1(22.6,24.91) v1(22.93,49.75) v1(22.93,48.46) v1(22.96,46.14) v1(22.97,44.93) v1(24.86,64.24) v1(25.09,0.76) v1(25.16,22.67) v1(25.16,21.82) v1(26.16,32.73) v1(26.16,22.67) v1(26.16,21.82) v1(26.16,16.86) v1(27.05,16.86) v1(27.16,22.67) v1(27.16,21.82) v1(27.4,64.24) v1(27.63,32.73) v1(27.81,54.88) v1(27.81,52.47) v1(28.06,16.86) v1(28.42,8.2) v1(28.7,25.04) v1(28.66,0.76) v1(29.08,29.48) v1(29.08,28.47) v1(29.08,27.58) v1(29.08,26.69) v1(29.08,25.8) v1(29.81,1.26) v1(29.94,64.24) v1(30.68,1.24) v1(31.26,0.78) v1(31.62,6.65) v1(31.69,33.67) v1(31.69,32.45) v1(31.87,8.53) v1(31.87,1.26) v1(32.48,64.24) v1(32.63,8.53) v1(32.71,1.26) v1(33.04,7.97) v1(33.27,0.78) v1(33.8,38.17) v1(33.88,1.26) v1(34.13,22.04) v1(34.16,22.85) v1(34.69,1.26) v1(35.02,64.24) v1(35.43,44.64) v1(35.43,43.83) v1(35.58,38.17) v1(35.55,22.5) v1(35.83,43.04) v1(35.83,41.77) v1(36.28,0.76) v1(36.93,22.85) v1(36.93,22.06) v1(37.56,64.24) v1(37.94,8.22) v1(38.27,36.44) v1(39.49,36.44) v1(40.1,64.24) v1(41.14,2.05) v1(41.4,41.42) v1(42.64,64.24) v1(42.79,39.9) v1(43.55,19.58) v1(43.68,39.9) v1(44.19,8.65) v1(44.19,7.51) v1(44.19,6.37) v1(44.19,5.35) v1(44.19,4.34) v1(44.57,46.5) v1(44.63,12.89) v1(44.7,20.73) v1(44.7,19.58) v1(44.81,2.42) v1(45.18,64.24) v1(45.23,15.13) v1(45.85,19.58) v1(46.22,39.9) v1(46.48,41.42) v1(47.01,16.73) v1(47.31,2.42) v1(47.62,57.8) v1(47.72,64.24) v1(49.4,23.13) v1(49.65,46.5) v1(50.26,64.24) v1(50.54,23.13) v1(50.54,16.02) v1(50.54,14.88) v1(50.67,17.54) v1(51.05,40.4) v1(51.56,41.42) v1(51.68,15.38) v1(51.68,14.37) v1(52.7,57.8) v1(52.8,64.24) v1(53.33,18.94) v1(53.37,20.34) v1(53.84,31.64) v1(53.97,29.99) v1(54.22,38.75) v1(54.73,46.5) v1(54.99,29.99) v1(55.34,64.24) v1(55.26,37.36) v1(55.26,36.11) v1(56,29.99) v1(56.64,41.42) v1(57.02,29.99) v1(57.78,57.8) v1(57.88,64.24) v1(58.8,30.24) v1(59.09,34.56) v3(46.1,59.83)
25814_ADCIN1: length 5.7
  TOP w0.203: 46.29,22.17 46.1,22.17 45.7,21.77 U0801.2
  TOP w0.508: 46.29,22.17 46.6,22.49 46.6,23.73 R7429.2 47,23.98 v1(47.49,24.47) R7427.1
25814_ADCIN2: length 5.7
  TOP w0.203: 45.53,22.31 45.53,22.13 45.3,21.9 U0801.3
  TOP w0.508: 45.53,22.31 45.84,22.63 R7428.2 45.7,22.97 45.21,23.46 45.21,24.91 v1(45.71,25.42) 45.97,25.67 R7426.1
25814_DEBUG: length 5.4
  TOP w0.127: U0801.6 44.1,21.81 43.81,22.1 43.81,25.16 v1(44.19,25.54) 44.23,25.54 R7425.2
25814_EC_IRQ: length 2
  TOP w0.127: R7440.2 41.61,21.39 v1(41.9,21.1) 42.03,20.97 42.16,20.97 42.56,20.58 U0801.10
25814_EC_SCL: length 4.1
  TOP w0.127: R7439.1 v1(41.23,23.51) 41.23,22.2 41.57,21.86 41.89,21.86 U0801.9
25814_EC_SDA: length 8.4
  TOP w0.127: U0801.8 43.3,21.81 42.95,22.17 v1(42.95,22.34) 43.3,22.7 43.3,28.76 R7437.1
+1P5V_LDO: length 1.6
  TOP w0.203: 44.9,22.17 U0801.4
  TOP w0.508: C3417.2 44.71,22.82 v1(44.71,22.35) 44.9,22.17
+3P3V_DSW: length 87
  TOP w0.508: 59.58,54.75 46.76,54.75 39.19,62.32 11.37,62.32 9.27,60.22 6.34,60.22 4.62,61.93 2.85,61.93 1.49,60.57 1.49,39.35 J1.21
+3P3V_LDO: length 12.9
  TOP w0.203: 46.74,21.72 46.62,21.61 46.21,21.61 U0801.1
  TOP w0.508: R7437.2 v1(43.94,27.83) R7430.1 ; R7431.1 v1(41.14,17.67) ; R7440.1 v1(41.12,19.9) ; R7426.2 v1(46.86,27.11) R7427.2 47.84,27.11 48.76,26.18 v1(48.76,25.54) 48.76,24.47 48.27,23.98 C3418.2 47.96,23.98 47.24,23.26 47.24,22.22 46.74,21.72 ; R7439.2 v1(42.73,24.27)
+3P3V_MUX1_S5: length 11.6
  TOP w0.203: U1001.6 13.82,21.41 v1(13.86,21.45) ; v1(7.11,18.69) 7.36,18.94 U1001.28 ; v1(7.66,23.33) 8.06,22.94 U1001.20 ; U1001.1 v1(13.16,18.88)
  TOP w0.508: R1008.2 v1(2.38,15.04) ; R1035.2 v1(12.31,30.37) ; R1005.2 v1(15.74,30.37) ; v1(3.04,7.38) R1021.2 R1023.2 R1034.2 ; R1006.2 4.29,14.52 v1(4.44,14.37) ; v1(5.33,18.94) R1004.2 ; R1036.2 v1(16.76,30.37) ; R1025.2 v1(6.34,16.65) ; R1027.2 v1(13.58,30.37)
  vias: v1(13.84,31.39) v1(14.73,31.39) v1(15.62,31.39)
+3P3V_S0: length 1.1
  TOP w0.508: v1(38.78,44.55) F0507.2
+3P3V_S5: length 59.9
  TOP w0.203: 47.28,20.98 U0801.32
  TOP w0.508: 47.28,20.98 47.87,21.57 C3414.2 48.04,21.7 48.76,22.41 48.76,23.51 49.46,24.21 v1(49.46,31.01) ; R1104.2 v1(31.49,21.61) ; R1014.2 5.7,19.61 v1(5.98,19.89) ; R0812.1 v1(42.03,30.88) 42.03,29.13 L0701.1 ; R0907.1 25.86,50.52 ; R7425.1 v1(44.95,30.88) ; v1(7.23,25.93) 6.85,26.31 R1103.2 ; R1015.2 v1(2.56,22.28) ; v1(19.55,33.8) 19.55,33.16 19.17,32.78 R7423.1 R1112.1 ; R0910.1 v1(26.16,60.09) ; R1040.1 v1(14.73,25.93)
  L3_IN1 w0.508: v1(7.23,25.93) 8.12,26.81 13.84,26.81 v1(14.73,25.93) ; v1(26.58,55.43) 26.16,55.85 v1(26.16,60.09)
  L4_VCC w0.508: 2.55,44.3 J1.15 ; J1.15 3.82,44.3 ; J1.15 3.82,43.03 ; J1.15 2.55,43.03
  BOTTOM w0.508: v1(30.35,30.62) 29.84,30.12 29.84,22.75 30.98,21.61 v1(31.49,21.61) ; 3.18,44.76 J1.13 ; J1.13 2.28,45.67 ; J1.13 4.08,45.67 ; 2.28,43.67 J1.15 ; J1.15 3.18,44.57 ; J1.15 3.18,42.76 ; J1.15 4.08,43.67
  vias: v1(15.23,34.43) v1(16,34.43) v1(26.03,51.83) v1(26.03,50.94) v1(26.79,50.94)
+3P3V_U7401_S5: length 11.7
  TOP w0.152: U0701.17 33.28,21.8 32.89,21.4 v1(32.79,21.4) ; U0701.13 33.08,23.2 v1(32.76,23.51) ; v1(38.37,23.59) 37.98,23.2 U0701.34 ; v1(38.35,21.3) 37.85,21.8 U0701.30
  TOP w0.508: R0706.2 v1(42.73,26.43) v1(42.73,25.29) R0707.2 ; R0704.2 R0705.2 32.06,20.68 v1(32.79,21.4) ; R0703.2 v1(40.13,19.88) ; L0701.2 v1(42.76,27.67) ; R0702.2 v1(39.11,19.91)
  vias: v1(31.87,24.78) v1(32.46,25.26) v1(32.51,24.53)
